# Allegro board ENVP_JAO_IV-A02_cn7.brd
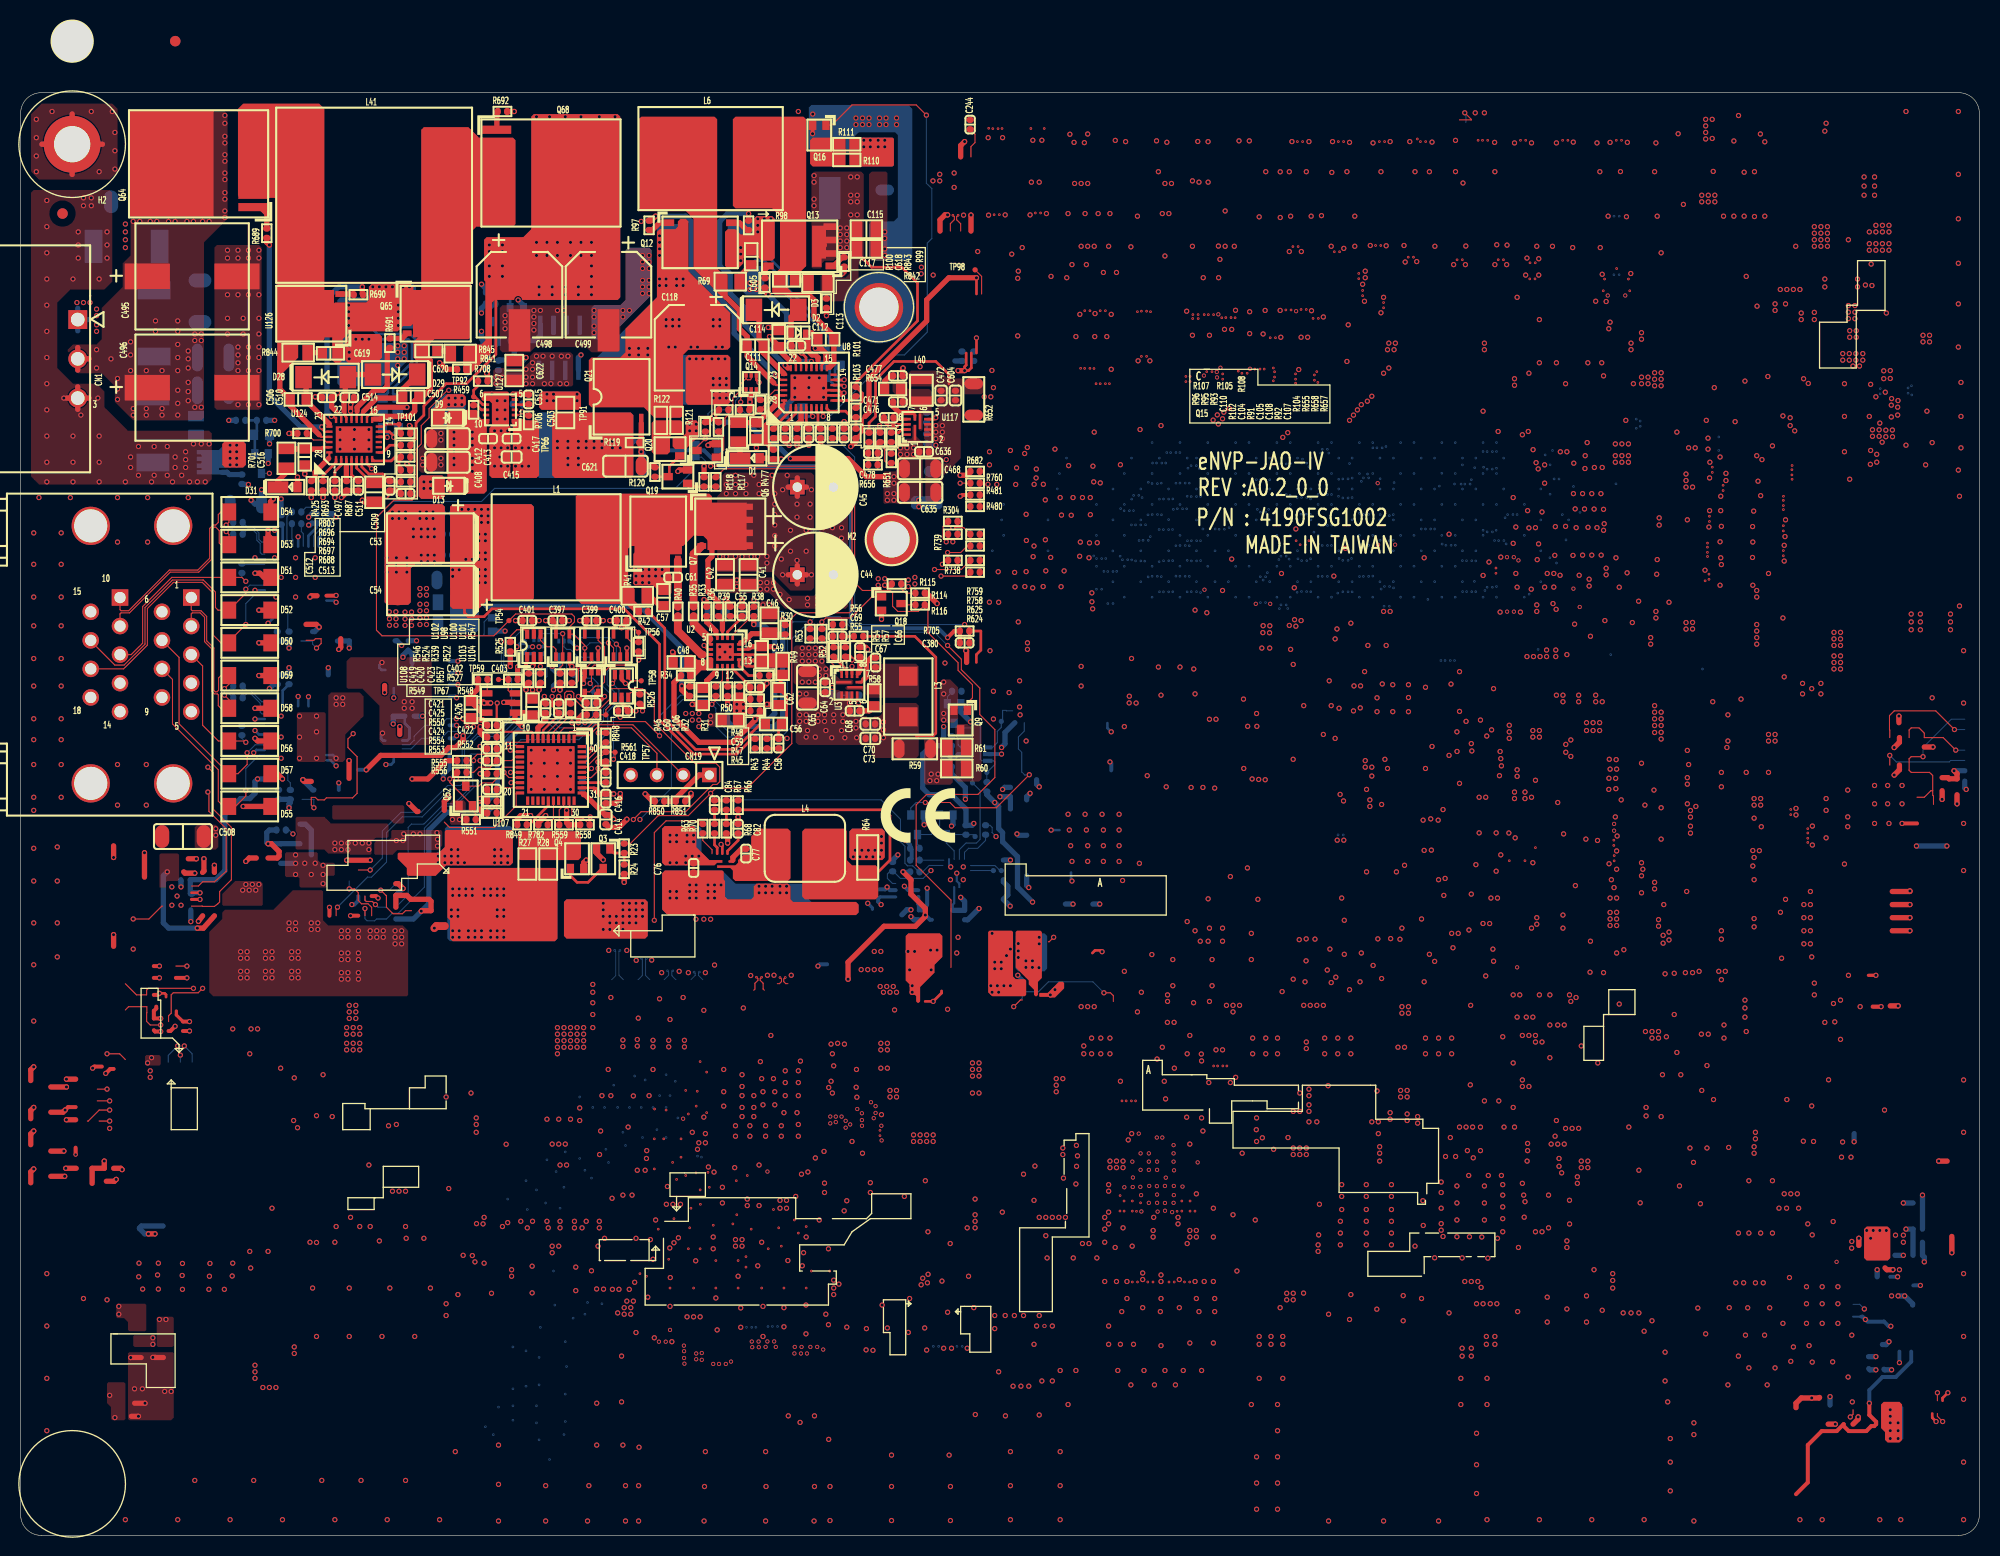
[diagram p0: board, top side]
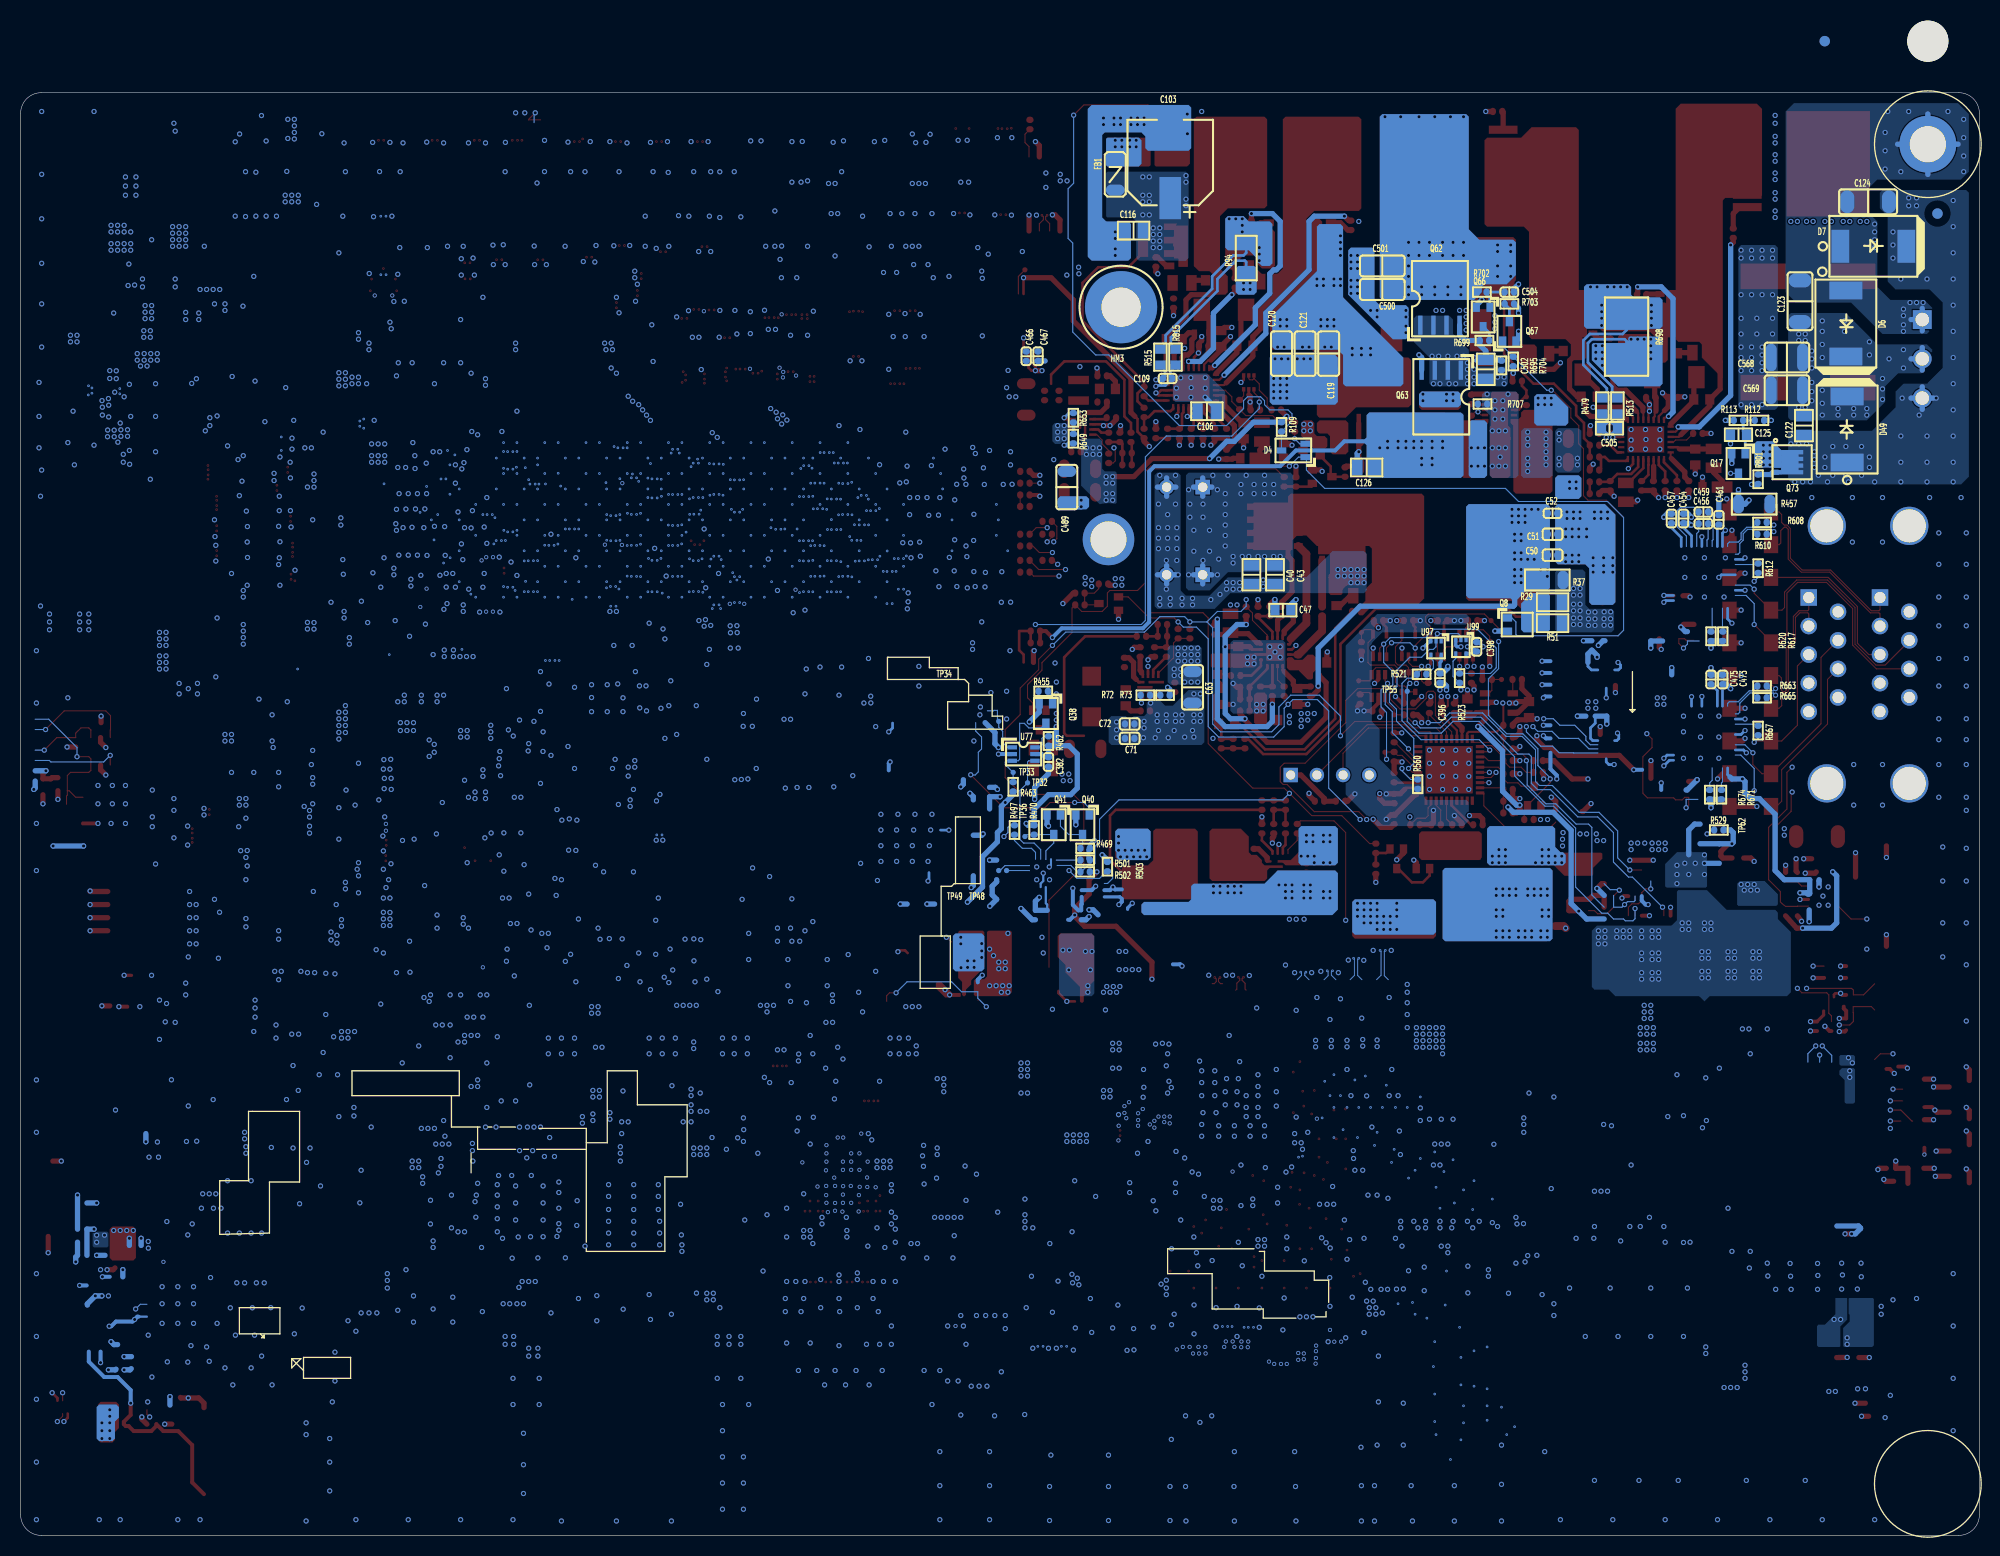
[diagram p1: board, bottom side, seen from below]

Outline 190 x 140 mm; copper layers: TOP, L2-GND1, L3-IN1, L4-VCC1, L5-VCC2, L6-IN2, L7-GND2, BOTTOM. Coordinates in mm from the lower left corner of the outline.
Outline path: 0,138 0,2 arc(0.59,0.59) 2,0 188,0 arc(189.41,0.59) 190,2 190,138 arc(189.41,139.41) 188,140 2,140 arc(0.59,139.41) 0,138

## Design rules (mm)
constraint set DEFAULT: min track width 0.102, pair gap 0.102
net group 5-6.5;3.5-3.5_DP_10.8-9: nets USB2_0_N_CON USB2_0_P_CON
net group 50OHM_RS485_D1_DP_8;8-8;8: nets D1- RX1/D1+
net group 50OHM_RS485_D2_DP_8;8-8;8: nets D2- RX2/D2+
net group 50OHM_RS485_RD1_DP_8;8-8;8: nets RS232_RD1 RS485_D1-
net group 50OHM_RS485_RD2_DP_8;8-8;8: nets RS232_RD2 RS485_D2-
net group 85OHM_M2B_USB3_RX_DP_13.1;10.A: nets M2B_USB3_RX_N M2B_USB3_RX_P
net group 85OHM_M2B_USB3_TX_DP_13.1;10.A: nets M2B_USB3_TX_N M2B_USB3_TX_P
net group 85OHM_M2E_PCIE_UPHY0_RX3_DP_1A: nets UPHY0_RX3_N UPHY0_RX3_P
net group 85OHM_M2E_PCIE_UPHY0_TX3_DP_1A: nets UPHY0_TX3_N UPHY0_TX3_P
net group 85OHM_M2E_PCIE_UPHY0_TX3_M2E_A: nets UPHY0_TX3_N_M2E UPHY0_TX3_P_M2E
net group 85OHM_M2E_UPHY0_SF_PCIE1_CLK_A: nets UPHY0_SF_PCIE1_CLK_N UPHY0_SF_PCIE1_CLK_P
net group 85OHM_MBGE_OSC_156MHZ_DP_32.4A: nets OSC_156MHZ_N OSC_156MHZ_P
net group 85OHM_MGBE_UPHY2_REFCLK2_DP_3A: nets UPHY2_REFCLK2_N UPHY2_REFCLK2_P
net group 85OHM_PCIE16_PCIE4_CLK_DP_10.A: nets PCIE4_CLK_N PCIE4_CLK_P
net group 85OHM_PCIE16_PCIE5_CLK_DP_10.A: nets PCIE5_CLK_N PCIE5_CLK_P
net group 85OHM_PCIE16_PEX_REFCLK_DP_10A: nets PEX_REFCLK_N PEX_REFCLK_P
net group 85OHM_PCIE16_PEX_TX10_DP_10.8A: nets PEX_TX10_N PEX_TX10_P
net group 85OHM_PCIE16_PEX_TX12_DP_10.8A: nets PEX_TX12_N PEX_TX12_P
net group 85OHM_PCIE16_PEX_TX14_DP_10.8A: nets PEX_TX14_N PEX_TX14_P
net group 85OHM_PCIE16_UPHY0_RX4_DP_10.A: nets UPHY0_RX4_N UPHY0_RX4_P
net group 85OHM_PCIE16_UPHY0_RX5_DP_10.A: nets UPHY0_RX5_N UPHY0_RX5_P
net group 85OHM_PCIE16_UPHY0_TX4_DP_10.A: nets UPHY0_TX4_N UPHY0_TX4_P
net group 85OHM_PCIE16_UPHY0_TX4_M2M_DPA: nets UPHY0_TX4_N_M2M UPHY0_TX4_P_M2M
net group 85OHM_PCIE16_UPHY0_TX5_DP_10.A: nets UPHY0_TX5_N UPHY0_TX5_P
net group 85OHM_PCIE16_UPHY0_TX5_M2M_DPA: nets UPHY0_TX5_N_M2M UPHY0_TX5_P_M2M
net group 85OHM_PCIE16_UPHY0_TX6_M2M_DPA: nets UPHY0_TX6_N_M2M UPHY0_TX6_P_M2M
net group 85OHM_PCIE16_UPHY0_TX7_M2M_DPA: nets UPHY0_TX7_N_M2M UPHY0_TX7_P_M2M
net group 85OHM_PCIE16_UPHY1_EP_REFCLK0A: nets UPHY1_EP_REFCLK0_N UPHY1_EP_REFCLK0_P
net group 85OHM_PCIE16_UPHY1_PEX_TX0_DPA: nets UPHY1_PEX_TX0_N UPHY1_PEX_TX0_P
net group 85OHM_PCIE16_UPHY1_PEX_TX1_DPA: nets UPHY1_PEX_TX1_N UPHY1_PEX_TX1_P
net group 85OHM_PCIE16_UPHY1_PEX_TX2_DPA: nets UPHY1_PEX_TX2_N UPHY1_PEX_TX2_P
net group 85OHM_PCIE16_UPHY1_PEX_TX3_DPA: nets UPHY1_PEX_TX3_N UPHY1_PEX_TX3_P
net group 85OHM_PCIE16_UPHY1_PEX_TX4_DPA: nets UPHY1_PEX_TX4_N UPHY1_PEX_TX4_P
net group 85OHM_PCIE16_UPHY1_PEX_TX5_DPA: nets UPHY1_PEX_TX5_N UPHY1_PEX_TX5_P
net group 85OHM_PCIE16_UPHY1_PEX_TX6_DPA: nets UPHY1_PEX_TX6_N UPHY1_PEX_TX6_P
net group 85OHM_PCIE16_UPHY1_PEX_TX7_DPA: nets UPHY1_PEX_TX7_N UPHY1_PEX_TX7_P
net group 85OHM_PCIE16_UPHY1_REFCLK0_DPA: nets UPHY1_REFCLK0_N UPHY1_REFCLK0_P
net group 85OHM_PCIE16_UPHY1_RX0_DP_10.A: nets UPHY1_RX0_N UPHY1_RX0_P
net group 85OHM_PCIE16_UPHY1_RX2_DP_10.A: nets UPHY1_RX2_N UPHY1_RX2_P
net group 85OHM_PCIE16_UPHY1_RX3_DP_10.A: nets UPHY1_RX3_N UPHY1_RX3_P
net group 85OHM_PCIE16_UPHY1_RX4_DP_10.A: nets UPHY1_RX4_N UPHY1_RX4_P
net group 85OHM_PCIE16_UPHY1_RX5_DP_10.A: nets UPHY1_RX5_N UPHY1_RX5_P
net group 85OHM_PCIE16_UPHY1_RX6_DP_10.A: nets UPHY1_RX6_N UPHY1_RX6_P
net group 85OHM_PCIE16_UPHY1_RX7_DP_10.A: nets UPHY1_RX7_N UPHY1_RX7_P
net group 85OHM_PCIE16_UPHY1_TX0_DP_10.A: nets UPHY1_TX0_N UPHY1_TX0_P
net group 85OHM_PCIE16_UPHY1_TX1_DP_10.A: nets UPHY1_TX1_N UPHY1_TX1_P
net group 85OHM_PCIE16_UPHY1_TX2_DP_10.A: nets UPHY1_TX2_N UPHY1_TX2_P
net group 85OHM_PCIE16_UPHY1_TX3_DP_10.A: nets UPHY1_TX3_N UPHY1_TX3_P
net group 85OHM_PCIE16_UPHY1_TX4_DP_10.A: nets UPHY1_TX4_N UPHY1_TX4_P
net group 85OHM_PCIE16_UPHY1_TX5_DP_10.A: nets UPHY1_TX5_N UPHY1_TX5_P
net group 85OHM_PCIE16_UPHY1_TX6_DP_10.A: nets UPHY1_TX6_N UPHY1_TX6_P
net group 85OHM_PCIE16_UPHY1_TX7_DP_10.A: nets UPHY1_TX7_N UPHY1_TX7_P
net group 85OHM_PCIE16_UPHY_RX7_DP_10.8A: nets UPHY_RX7_N UPHY_RX7_P
net group 85OHM_PCIE16_UPHY_RX8_DP_10.8A: nets UPHY_RX8_N UPHY_RX8_P
net group 85OHM_PCIE16_UPHY_RX9_DP_10.8A: nets UPHY_RX9_N UPHY_RX9_P
net group 85OHM_PCIE16_UPHY_RX10_DP_10.A: nets UPHY_RX10_N UPHY_RX10_P
net group 85OHM_PCIE16_UPHY_RX11_DP_10.A: nets UPHY_RX11_N UPHY_RX11_P
net group 85OHM_PCIE16_UPHY_TX8_DP_10.8A: nets UPHY_TX8_N UPHY_TX8_P
net group 85OHM_PCIE16_UPHY_TX9_DP_10.8A: nets UPHY_TX9_N UPHY_TX9_P
net group 85OHM_PCIE16_UPHY_TX10_DP_10.A: nets UPHY_TX10_N UPHY_TX10_P
net group 85OHM_PCIE16_UPHY_TX11_DP_10.A: nets UPHY_TX11_N UPHY_TX11_P
net group 85OHM_PCIE_16UPHY_TX7_DP_10.8A: nets UPHY_TX7_N UPHY_TX7_P
net group 85OHM_PCUE16_UPHY1_RX1_DP_10.A: nets UPHY1_RX1_N UPHY1_RX1_P
net group 85OHM_TYPEC_UPHY_TX0_DP_13.1;A: nets UPHY_TX0_N UPHY_TX0_P
net group 85OHM_TYPEC_USB_UPHY_RX0_DP_1A: nets UPHY_RX0_N UPHY_RX0_P
net group 85OHM_TYPEC_USBC1_RX1_DUT_CONA: nets USBC1_RX1_DUT_N_CON USBC1_RX1_DUT_P_CON
net group 85OHM_TYPEC_USBC1_RX1_DUT_DP_A: nets USBC1_RX1_DUT_N USBC1_RX1_DUT_P
net group 85OHM_TYPEC_USBC1_RX2_DUT_CONA: nets USBC1_RX2_DUT_N_CON USBC1_RX2_DUT_P_CON
net group 85OHM_TYPEC_USBC1_RX2_DUT_DP_A: nets USBC1_RX2_DUT_N USBC1_RX2_DUT_P
net group 85OHM_TYPEC_USBC1_TX1_DU2_CONA: nets USBC1_TX1_DU2_N_CON USBC1_TX1_DU2_P_CON
net group 85OHM_TYPEC_USBC1_TX1_DUT_AC_A: nets USBC1_TX1_DUTN USBC1_TX1_DUTP
net group 85OHM_TYPEC_USBC1_TX1_DUT_CONA: nets USBC1_TX1_DUT_N_CON USBC1_TX1_DUT_P_CON
net group 85OHM_TYPEC_USBC1_TX1_DUT_DP_A: nets USBC1_TX1_DUT_N USBC1_TX1_DUT_P
net group 85OHM_TYPEC_USBC1_TX2_DUT_AC_A: nets USBC1_TX2_DUT_N USBC1_TX2_DUT_P
net group 85OHM_TYPEC_USBC1_TX2_DUT_DP_A: nets USBC1_TX2_DUTN USBC1_TX2_DUTP
net group 85OHM_UPHY_RX_1_DP_13.1;10.8-A: nets UPHY_RX1_N UPHY_RX1_P
net group 85OHM_UPHY_TX1_DP_13.1;10.8-1A: nets UPHY_TX1N UPHY_TX1P
net group 85OHM_UPHY_TX_1_DP_13.1;10.8-A: nets UPHY_TX1_N UPHY_TX1_P
net group 85OHM_USBHIB_US_USBSS_TX_HUB_A: nets USBSS_TX_HUB_N USBSS_TX_HUB_P
net group 85OHM_USBHUB_DSP1_SSRX_DP_13.A: nets DSP1_SSRX_N DSP1_SSRX_P
net group 85OHM_USBHUB_DSP1_SSTX_DP_13.A: nets DSP1_SSTX_N DSP1_SSTX_P
net group 85OHM_USBHUB_DSP2_SSRX_DP_13.A: nets DSP2_SSRX_N DSP2_SSRX_P
net group 85OHM_USBHUB_DSP2_SSTX_DP_13.A: nets DSP2_SSTX_N DSP2_SSTX_P
net group 85OHM_USBHUB_DSP3_SSRX_DP_13.A: nets DSP3_SSRX_N DSP3_SSRX_P
net group 85OHM_USBHUB_DSP3_SSTX_DP_13.A: nets DSP3_SSTX_N DSP3_SSTX_P
net group 85OHM_USBHUB_DSP4_SSRX_DP_13.A: nets DSP4_SSRX_N DSP4_SSRX_P
net group 85OHM_USBHUB_DSP4_SSTX_DP_13.A: nets DSP4_SSTX_N DSP4_SSTX_P
net group 85OHM_USBHUB_US_UPHY0_RX2_DP_A: nets UPHY0_RX2_N UPHY0_RX2_P
net group 85OHM_USBHUB_US_UPHY0_TX2_DP_A: nets UPHY0_TX2_N UPHY0_TX2_P
net group 85OHM_USBHUB_US_UPHY_0_TX2_DPA: nets UPHY_0_TX2_N UPHY_0_TX2_P
net group 85OHM_USBHUB_US_USBSS0_TX_HUBA: nets USBSS0_TX_HUB_N USBSS0_TX_HUB_P
net group 85OHM_USBHUB_US_USBSS_RX_HUB_A: nets USBSS_RX_HUB_N USBSS_RX_HUB_P
net group 85OHM_USBHUB_USBSS_RX_A_CON1_A: nets USBSS_RX_A_CON1_N USBSS_RX_A_CON1_P
net group 85OHM_USBHUB_USBSS_RX_A_CON2_A: nets USBSS_RX_A_CON2_N USBSS_RX_A_CON2_P
net group 85OHM_USBHUB_USBSS_RX_B_CON3_A: nets USBSS_RX_B_CON3_N USBSS_RX_B_CON3_P
net group 85OHM_USBHUB_USBSS_RX_B_CON4_A: nets USBSS_RX_B_CON4_N USBSS_RX_B_CON4_P
net group 85OHM_USBHUB_USBSS_TX_A_1_DP_A: nets USBSS_TX_A_1_N USBSS_TX_A_1_P
net group 85OHM_USBHUB_USBSS_TX_A_2_DP_A: nets USBSS_TX_A_2_N USBSS_TX_A_2_P
net group 85OHM_USBHUB_USBSS_TX_A_CON1_A: nets USBSS_TX_A_CON1_N USBSS_TX_A_CON1_P
net group 85OHM_USBHUB_USBSS_TX_A_CON2_A: nets USBSS_TX_A_CON2_N USBSS_TX_A_CON2_P
net group 85OHM_USBHUB_USBSS_TX_B_3_DP_A: nets USBSS_TX_B_3_N USBSS_TX_B_3_P
net group 85OHM_USBHUB_USBSS_TX_B_4_DP_A: nets USBSS_TX_B_4_N USBSS_TX_B_4_P
net group 85OHM_USBHUB_USBSS_TX_B_CON3_A: nets USBSS_TX_B_CON3_N USBSS_TX_B_CON3_P
net group 85OHM_USBHUB_USBSS_TX_B_CON4_A: nets USBSS_TX_B_CON4_N USBSS_TX_B_CON4_P
net group 90OHM_FORCE_USB2_0_DP_10.8;10A: nets USB2_0_N USB2_0_P
net group 90OHM_M2B_USB2_0_D_DP_10.8;10A: nets USB2_1_DN USB2_1_DP
net group 90OHM_M2B_USB_D_DP_10.8;10.8-A: nets M2B_USB_DN M2B_USB_DP
net group 90OHM_M2E_USB2_2_DP_10.8;10.8A: nets USB2_2_N USB2_2_P
net group 90OHM_USBHUB_DSP1_D_DP_10.8;1A: nets DSP1_DN DSP1_DP
net group 90OHM_USBHUB_DSP2_D_DP_10.8;1A: nets DSP2_DN DSP2_DP
net group 90OHM_USBHUB_DSP3_D_DP_10.8;1A: nets DSP3_DN DSP3_DP
net group 90OHM_USBHUB_DSP4_D_DP_10.8;1A: nets DSP4_DN DSP4_DP
net group 90OHM_USBHUB_USB1_A_DP_10.8;1A: nets USB1_A_N USB1_A_P
net group 90OHM_USBHUB_USB2_3_DP_10.8;1A: nets USB2_3_N USB2_3_P
net group 90OHM_USBHUB_USB2_3_HUB_DP_10A: nets USB2_3_HUB_N USB2_3_HUB_P
net group 90OHM_USBHUB_USB2_A_DP_10.8;1A: nets USB2_A_N USB2_A_P
net group 90OHM_USBHUB_USB3_B_DP_10.8;1A: nets USB3_B_N USB3_B_P
net group 90OHM_USBHUB_USB4_B_DP_10.8;1A: nets USB4_B_N USB4_B_P
net group 100OHM_CSI_0_CLK_DP_8.1;8.1-9;9: nets CSI_0_CLK_N CSI_0_CLK_P
net group 100OHM_CSI_0_D0_DP_8.1;8.1-9;9: nets CSI_0_D0_N CSI_0_D0_P
net group 100OHM_CSI_0_D1_DP_8.1;8.1-9;9: nets CSI_0_D1_N CSI_0_D1_P
net group 100OHM_CSI_1_CLK_DP_8.1;8.1-9;9: nets CSI_1_CLK_N CSI_1_CLK_P
net group 100OHM_CSI_1_D0_DP_8.1;8.1-9;9: nets CSI_1_D0_N CSI_1_D0_P
net group 100OHM_CSI_1_D1_DP_8.1;8.1-9;9: nets CSI_1_D1_N CSI_1_D1_P
net group 100OHM_CSI_2_CLK_DP_8.1;8.1-9;9: nets CSI_2_CLK_N CSI_2_CLK_P
net group 100OHM_CSI_2_D0_DP_8.1;8.1-9;9: nets CSI_2_D0_N CSI_2_D0_P
net group 100OHM_CSI_2_D1_DP_8.1;8.1-9;9: nets CSI_2_D1_N CSI_2_D1_P
net group 100OHM_CSI_3_CLK_DP_8.1;8.1-9;9: nets CSI_3_CLK_N CSI_3_CLK_P
net group 100OHM_CSI_3_D0_DP_8.1;8.1-9;9: nets CSI_3_D0_N CSI_3_D0_P
net group 100OHM_CSI_3_D1_DP_8.1;8.1-9;9: nets CSI_3_D1_N CSI_3_D1_P
net group 100OHM_CSI_4_CLK_DP_8.1;8.1-9;9: nets CSI_4_CLK_N CSI_4_CLK_P
net group 100OHM_CSI_4_D0_DP_8.1;8.1-9;9: nets CSI_4_D0_N CSI_4_D0_P
net group 100OHM_CSI_4_D1_DP_8.1;8.1-9;9: nets CSI_4_D1_N CSI_4_D1_P
net group 100OHM_CSI_5_CLK_DP_8.1;8.1-9;9: nets CSI_5_CLK_N CSI_5_CLK_P
net group 100OHM_CSI_5_D0_DP_8.1;8.1-9;9: nets CSI_5_D0_N CSI_5_D0_P
net group 100OHM_CSI_5_D1_DP_8.1;8.1-9;9: nets CSI_5_D1_N CSI_5_D1_P
net group 100OHM_CSI_6_CLK_DP_8.1;8.1-9;9: nets CSI_6_CLK_N CSI_6_CLK_P
net group 100OHM_CSI_6_D0_DP_8.1;8.1-9;9: nets CSI_6_D0_N CSI_6_D0_P
net group 100OHM_CSI_6_D1_DP_8.1;8.1-9;9: nets CSI_6_D1_N CSI_6_D1_P
net group 100OHM_CSI_7_CLK_DP_8.1;8.1-9;9: nets CSI_7_CLK_N CSI_7_CLK_P
net group 100OHM_CSI_7_D0_DP_8.1;8.1-9;9: nets CSI_7_D0_N CSI_7_D0_P
net group 100OHM_CSI_7_D1_DP_8.1;8.1-9;9: nets CSI_7_D1_N CSI_7_D1_P
net group 100OHM_GBE_PHY1_A_DP_10.8;10.A: nets GBE_PHY1_A_N GBE_PHY1_A_P
net group 100OHM_GBE_PHY1_B_DP_10.8;10.A: nets GBE_PHY1_B_N GBE_PHY1_B_P
net group 100OHM_GBE_PHY1_C_DP_10.8;10.A: nets GBE_PHY1_C_N GBE_PHY1_C_P
net group 100OHM_GBE_PHY1_D_DP_10.8;10.A: nets GBE_PHY1_D_N GBE_PHY1_D_P
net group 100OHM_GBE_PHY2_A_DP_10.8;10.A: nets GBE_PHY2_A_N GBE_PHY2_A_P
net group 100OHM_GBE_PHY2_B_DP_10.8;10.A: nets GBE_PHY2_B_N GBE_PHY2_B_P
net group 100OHM_GBE_PHY2_C_DP_10.8;10.A: nets GBE_PHY2_C_N GBE_PHY2_C_P
net group 100OHM_GBE_PHY2_D_DP_10.8;10.A: nets GBE_PHY2_D_N GBE_PHY2_D_P
net group 100OHM_HDMI_DP0_CLK_DP_13.5;1A: nets HDMI_DP0_CLKN HDMI_DP0_CLKP
net group 100OHM_HDMI_DP0_TX0_DP_13.5;1A: nets HDMI_DP0_TX0N HDMI_DP0_TX0P
net group 100OHM_HDMI_DP0_TX1_DP_13.5;1A: nets HDMI_DP0_TX1N HDMI_DP0_TX1P
net group 100OHM_HDMI_DP0_TX2_DP_13.5;1A: nets HDMI_DP0_TX2N HDMI_DP0_TX2P
net group 100OHM_MGBE_PCIE_AQR113C_RX_DA: nets AQR113C_RX_N AQR113C_RX_P
net group 100OHM_MGBE_PCIE_AQR113C_TX_DA: nets AQR113C_TX_N AQR113C_TX_P
net group 100OHM_MGBE_PCIE_UPHY_RX6_DP_A: nets UPHY_RX6_N UPHY_RX6_P
net group 100OHM_RE_HDMI_CLK_DP_13.5;13A: nets RE_HDMI_DP0_CLKN RE_HDMI_DP0_CLKP
net group 100OHM_RE_HDMI_TX0_DP_13.5;13A: nets RE_HDMI_DP0_TX0N RE_HDMI_DP0_TX0P
net group 100OHM_RE_HDMI_TX1_DP_13.5;13A: nets RE_HDMI_DP0_TX1N RE_HDMI_DP0_TX1P
net group 100OHM_RE_HDMI_TX2_DP_13.5;13A: nets RE_HDMI_DP0_TX2N RE_HDMI_DP0_TX2P
net group 100OHM_RE_OUT_HDMI_DP0_CLK_DPA: nets OUT_HDMI_DP0_CLKN OUT_HDMI_DP0_CLKP
net group 100OHM_RE_OUT_HDMI_DP0_TX0_DPA: nets OUT_HDMI_DP0_TX0N OUT_HDMI_DP0_TX0P
net group 100OHM_RE_OUT_HDMI_DP0_TX1_DPA: nets OUT_HDMI_DP0_TX1N OUT_HDMI_DP0_TX1P
net group 120OHM_CAN_BUS_DB9_DP_10.5;10A: nets CANH_DB9 CANL_DB9
net group 120OHM_CAN_BUS_DP_10.5;10.5-6;6: nets CANH CANL
net group DIFF_AUD_HPO_DP_10;10-10;10: nets AUD_HPOL AUD_HPOR
net group DIFF_AUD_HPO_HDA_DP_10;10-10;10: nets AUD_HPOL_HDA AUD_HPOR_HDA
net group GPIO24_XFI2_MDIO_12;12-10.5;1A: nets GPIO24_XFI2_MDIO GPIO24_XFI2_MDIO_CVM
net group I2S1_DIN_8;8-7;7: nets I2S1_DIN I2S1_DIN_CDC
net group I2S1_DOUT_8;8-7;7: nets I2S1_DOUT I2S1_DOUT_CDC
net group I2S1_FS_8;8-7;7: nets I2S1_FS I2S1_FS_CDC
net group I2S1_SCLK_8;8-7;7: nets I2S1_SCLK I2S1_SCLK_CDC
net group MGBE-M: nets UPHY_TX6_N UPHY_TX6_P
net group RE_OUT_HDMI_DP0_TX2_DP_13.5;1A: nets OUT_HDMI_DP0_TX2N OUT_HDMI_DP0_TX2P
net group USB2: nets USB2_1_N USB2_1_P
net group 1V2_DCVDD_15;15-15;15: nets 1V2_DCVDD
net group 1V8_AVDD_15;15-15;15: nets 1V8_AVDD
net group 1V8_CPVDD_15;15-15;15: nets 1V8_CPVDD
net group 3V3_AO_BODE_12;12-10.5;10.5: nets 3V3_AO_BODE
net group 3V3_AO_FB_12;12-10.5;10.5: nets 3V3_AO_FB
net group 3V3_AO_FB_R_12;12-10.5;10.5: nets 3V3_AO_FB_R
net group 5V_SPKVDD_30;30-30;30: nets 5V_SPKVDD
net group 15-15: nets AUDIO_VREF_DAC
net group AUD_MCLK01_CDC_8;8-7;7: nets AUD_MCLK01_CDC
net group AUDIO_JD1_12;12-10.5;10.5: nets AUDIO_JD1
net group BAT_CONN_LIM_20;20-20;20: nets BAT_CONN_LIM
net group BT_DEV_WAKE_M2E_12;12-10.5;10.5: nets BT_DEV_WAKE_M2E
net group BT_RST_N_M2E_CON_12;12-10.5;1A: nets BT_RST_N_M2E_CON
net group BT_WAKE_AP_M2E_CON_12;12-10.5A: nets BT_WAKE_AP_M2E_CON
net group BUCK_1V1_BODE_12;12-10.5;10.5: nets BUCK_1V1_BODE
net group BUCK_1V1_FB_12;12-10.5;10.5: nets BUCK_1V1_FB
net group BUCK_1V1_FB_R_12;12-10.5;10.5: nets BUCK_1V1_FB_R
net group BUTTON_POWER_ON_N_12;12-10.5;A: nets BUTTON_POWER_ON_N
net group BUTTON_POWER_ON_N_CON_12;12-1A: nets BUTTON_POWER_ON_N_CON
net group BUTTON_POWER_ON_N_KEY_12;12-1A: nets BUTTON_POWER_ON_N_KEY
net group CAM0_RST_12;12-10.5;10.5: nets CAM0_RST
net group CAM1_RST_12;12-10.5;10.5: nets CAM1_RST
net group CAM_2V8_BODE_12;12-10.5;10.5: nets CAM_2V8_BODE
net group CAM_2V8_FB_12;12-10.5;10.5: nets CAM_2V8_FB
net group CAM_2V8_FB_R_12;12-10.5;10.5: nets CAM_2V8_FB_R
net group CAM_BACKLIGHT_PWM_12;12-10.5;A: nets CAM_BACKLIGHT_PWM
net group CAM_SPI_CS0_8.1;8.1-6;6: nets CAM_SPI_CS0
net group CAM_SPI_MISO_8.1;8.1-6;6: nets CAM_SPI_MISO
net group CAM_SPI_MOSI_8.1;8.1-6;6: nets CAM_SPI_MOSI
net group CAM_SPI_SCK_8.1;8.1-6;6: nets CAM_SPI_SCK
net group CAN0_DIN_12;12-10.5;10.5: nets CAN0_DIN
net group CAN0_DOUT_12;12-10.5;10.5: nets CAN0_DOUT
net group CARRIER_POWER_ON_12;12-10.5;1A: nets CARRIER_POWER_ON
net group CARRIER_SHUTDOWN_N_12;12-10.5A: nets CARRIER_SHUTDOWN_N
net group CLK_32K_OSC_M2E_12;12-10.5;10.5: nets CLK_32K_OSC_M2E
net group CLK_32K_OSC_M2M_12;12-10.5;10.5: nets CLK_32K_OSC_M2M
net group COM_20;20-20;20: nets COM
net group CVM_PRSNT_12;12-10.5;10.5: nets CVM_PRSNT
net group DC_IN_EC_N_12;12-10.5;10.5: nets DC_IN_EC_N
net group DC_IN_GATE_CCG4_12;12-10.5;10.5: nets DC_IN_GATE_CCG4 DC_IN_GATE_CCG4_CTRL DC_IN_GATE_OE
net group DC_SRC_SEL_12;12-10.5;10.5: nets DC_SRC_SEL
net group DI_1_20;20-20;20: nets DI_1
net group DI_2_20;20-20;20: nets DI_2
net group DI_3_20;20-20;20: nets DI_3
net group DI_4_20;20-20;20: nets DI_4
net group DO1_OUT_40;40-40;40: nets DO1_OUT
net group DO2_OUT_40;40-40;40: nets DO2_OUT
net group DO3_OUT_40;40-40;40: nets DO3_OUT
net group DO4_OUT_40;40-40;40: nets DO4_OUT
net group DP1_HPD_GP77_XFI3_MDIO_12;12-A: nets DP1_HPD_GP77_XFI3_MDIO
net group DP2_AUX_CH_N_I2C6_DAT_8;8-7;7: nets DP2_AUX_CH_N_I2C6_DAT
net group DP2_AUX_CH_P_I2C6_CLK_8;8-7;7: nets DP2_AUX_CH_P_I2C6_CLK
net group DP2_HPD_CH0_HPD_12;12-10.5;10.5: nets DP2_HPD_CH0_HPD
net group DP2_HPD_GP80_XFI3_MDC_12;12-1A: nets DP2_HPD_GP80_XFI3_MDC
net group ECSPI2_CS0_8.1;8.1-6;6: nets ECSPI2_SS0
net group ECSPI2_CS0_LV_8.1;8.1-6;6: nets ECSPI2_SS0_LV
net group ECSPI2_MISO_8.1;8.1-6;6: nets ECSPI2_MISO
net group ECSPI2_MISO_LV_8.1;8.1-6;6: nets ECSPI2_MISO_LV
net group ECSPI2_MOSI_8.1;8.1-6;6: nets ECSPI2_MOSI
net group ECSPI2_MOSI_LV_8.1;8.1-6;6: nets ECSPI2_MOSI_LV
net group ECSPI2_SCLK_8.1;8.1-6;6: nets ECSPI2_SCLK
net group ECSPI2_SCLK_LV_8.1;8.1-6;6: nets ECSPI2_SCLK_LV
net group EFM8_FORCE_SHUTDOWN_12;12-10.A: nets EFM8_FORCE_SHUTDOWN
net group EFM8_MODULE_POWER_ON_12;12-10A: nets EFM8_MODULE_POWER_ON
net group EFM8_PSHOLD_12;12-10.5;10.5: nets EFM8_PSHOLD
net group EFM8_RST_MON_12;12-10.5;10.5: nets EFM8_RST_MON
net group EFM8SB10_C2CK_12;12-10.5;10.5: nets EFM8SB10_C2CK
net group ETH_WOL_EN_N_12;12-10.5;10.5: nets ETH_WOL_EN_N
net group ETH_WOL_EN_STATUS_12;12-10.5;A: nets ETH_WOL_EN_STATUS
net group FAN_PWM_12;12-10.5;10.5: nets FAN_PWM
net group FORCE_RECOVERY_N_12;12-10.5;1A: nets FORCE_RECOVERY_N
net group FORCE_RECOVERY_N_CON_12;12-10A: nets FORCE_RECOVERY_N_CON
net group FORCE_RECOVERY_N_KEY_12;12-10A: nets FORCE_RECOVERY_N_KEY
net group GB_AVDDH_10;10-10;10: nets GB_AVDDH
net group GB_MDC_12;12-10.5;10.5: nets GB_MDC
net group GB_MDIO_12;12-10.5;10.5: nets GB_MDIO
net group GB_PHY_RST_N_12;12-10.5;10.5: nets GB_PHY_RST_N
net group GB_PHY_RSTN_12;12-10.5;10.5: nets GB_PHY_RSTN
net group GB_RX_CTL_12;12-10.5;10.5: nets GB_RX_CTL
net group GB_RXC_12;12-10.5;10.5: nets GB_RXC
net group GB_RXD0_12;12-10.5;10.5: nets GB_RXD0
net group GB_RXD1_12;12-10.5;10.5: nets GB_RXD1
net group GB_RXD2_12;12-10.5;10.5: nets GB_RXD2
net group GB_RXD3_12;12-10.5;10.5: nets GB_RXD3
net group GB_TX_CTL_12;12-10.5;10.5: nets GB_TX_CTL
net group GB_TXC_12;12-10.5;10.5: nets GB_TXC
net group GB_TXD0_12;12-10.5;10.5: nets GB_TXD0
net group GB_TXD1_12;12-10.5;10.5: nets GB_TXD1
net group GB_TXD2_12;12-10.5;10.5: nets GB_TXD2
net group GB_TXD3_12;12-10.5;10.5: nets GB_TXD3
net group GP_PWM4*_12;12-10.5;10.5: nets GP_PWM4*
net group GP_PWM4_12;12-10.5;10.5: nets GP_PWM4
net group GPIO03_XFI2_MDC_12;12-10.5;10.5: nets GPIO03_XFI2_MDC
net group GPIO19_XFI1_MDC_12;12-10.5;10.5: nets GPIO19_XFI1_MDC
net group GPIO25_XFI0_MDIO_12;12-10.5;1A: nets GPIO25_XFI0_MDIO
net group GPIO26_XFI0_MDC_12;12-10.5;10.5: nets GPIO26_XFI0_MDC
net group GPIO33_XFI1_MDIO_12;12-10.5;1A: nets GPIO33_XFI1_MDIO
net group GPIO_PMOS_ON_12;12-10.5;10.5: nets GPIO_PMOS_ON
net group GPIO_PMOS_ON_CTRL_12;12-10.5;A: nets GPIO_PMOS_ON_CTRL
net group HDMI: nets HDMI_CLKN_CN HDMI_CLKP_CN HDMI_DP0_CLK_N HDMI_DP0_CLK_P HDMI_DP0_TX0_N HDMI_DP0_TX0_P HDMI_DP0_TX1_N HDMI_DP0_TX1_P HDMI_DP0_TX2_N HDMI_DP0_TX2_P HDMI_TX0_N HDMI_TX0_P HDMI_TX1_N HDMI_TX1_P HDMI_TX2_N HDMI_TX2_P
net group HDMI_DDC_SCL_CN_8;8-7;7: nets HDMI_DDC_SCL_CN
net group HDMI_DDC_SDA_CN_8;8-7;7: nets HDMI_DDC_SDA_CN
net group HUB_I2C_CLK_8;8-7;7: nets HUB_I2C_CLK
net group HUB_I2C_DAT_8;8-7;7: nets HUB_I2C_DAT
net group I2C_CLK_M2E_8;8-7;7: nets I2C_CLK_M2E
net group I2C_GP1_CLK_8;8-7;7: nets I2C_GP1_CLK
net group I2C_GP1_DAT_8;8-7;7: nets I2C_GP1_DAT
net group I2C_GP2_CLK_3V3_8;8-7;7: nets I2C_GP2_CLK_3V3
net group I2C_GP2_CLK_8;8-7;7: nets I2C_GP2_CLK
net group I2C_GP2_CLK_IO_8;8-7;7: nets I2C_GP2_CLK_IO
net group I2C_GP2_CLK_M2M_8;8-7;7: nets I2C_GP2_CLK_M2M
net group I2C_GP2_DAT_3V3_8;8-7;7: nets I2C_GP2_DAT_3V3
net group I2C_GP2_DAT_8;8-7;7: nets I2C_GP2_DAT
net group I2C_GP2_DAT_IO_8;8-7;7: nets I2C_GP2_DAT_IO
net group I2C_GP2_DAT_M2M_8;8-7;7: nets I2C_GP2_DAT_M2M
net group I2C_GP3_CLK_8;8-7;7: nets I2C_GP3_CLK
net group I2C_GP3_CLK_PEX_3V3_8;8-7;7: nets I2C_GP3_CLK_PEX_3V3
net group I2C_GP3_DAT_8;8-7;7: nets I2C_GP3_DAT
net group I2C_GP3_DAT_PEX_3V3_8;8-7;7: nets I2C_GP3_DAT_PEX_3V3
net group I2C_GP8_CLK_8;8-7;7: nets I2C_GP8_CLK
net group I2C_GP8_DAT_8;8-7;7: nets I2C_GP8_DAT
net group I2C_GP9_CLK_8;8-7;7: nets I2C_GP9_CLK
net group I2C_GP9_DAT_8;8-7;7: nets I2C_GP9_DAT
net group I2C_SCL_CDC_8;8-7;7: nets I2C_SCL_CDC
net group I2C_SDA_CDC_8;8-7;7: nets I2C_SDA_CDC
net group I2C_SDA_M2E_8;8-7;7: nets I2C_SDA_M2E
net group I2S4_DIN_8;8-7;7: nets I2S4_DIN
net group I2S4_DOUT_8;8-7;7: nets I2S4_DOUT
net group I2S4_FS_8;8-7;7: nets I2S4_FS
net group I2S4_SCLK_8;8-7;7: nets I2S4_SCLK
net group IO_EXPAN_P3_8;8-7;7: nets IO_EXPAN_P3
net group IO_EXPAN_P5_12;12-10.5;10.5: nets IO_EXPAN_P5
net group IO_EXPAN_RSTN_12;12-10.5;10.5: nets IO_EXPAN_RSTN
net group JTAG_TCK_12;12-10.5;10.5: nets JTAG_TCK
net group JTAG_TDI_4;12-3.5;10.5: nets JTAG_TDI
net group JTAG_TDO_4;12-3.5;10.5: nets JTAG_TDO
net group JTAG_TMS_4;12-3.5;10.5: nets JTAG_TMS
net group JTAG_TRST_N_12;12-10.5;10.5: nets JTAG_TRST_N
net group M2_B_RST#_8;8-7;7: nets M2_B_RST#
net group M2B_RST#_12;12-10.5;10.5: nets M2B_RST#
net group M2B_RST_#_12;12-10.5;10.5: nets M2B_RST_#
net group M2B_USIM_CLK_12;12-10.5;10.5: nets M2B_USIM_CLK
net group M2E_SDIO_CLK_12;12-10.5;10.5: nets M2E_SDIO_CLK
net group M2E_SDIO_CMD_4;12-3.5;10.5: nets M2E_SDIO_CMD
net group M2E_SDIO_D0_4;12-3.5;10.5: nets M2E_SDIO_D0
net group M2E_SDIO_D1_4;12-3.5;10.5: nets M2E_SDIO_D1
net group M2E_SDIO_D2_4;12-3.5;10.5: nets M2E_SDIO_D2
net group M2E_SDIO_D3_4;12-3.5;10.5: nets M2E_SDIO_D3
net group MCLK01_AUDIO_MCLK_8;8-7;7: nets MCLK01_AUDIO_MCLK
net group MCLK02_CAM0_MCLK_12;12-10.5;1A: nets MCLK02_CAM0_MCLK
net group MCLK02_MCLK_12;12-10.5;10.5: nets MCLK02_MCLK
net group MCLK03_CAM1_MCLK_12;12-10.5;1A: nets MCLK03_CAM1_MCLK
net group MCLK03_MCLK_12;12-10.5;10.5: nets MCLK03_MCLK
net group MCLK04_CAM2_MCLK_12;12-10.5;1A: nets MCLK04_CAM2_MCLK
net group MCLK04_MCLK_12;12-10.5;10.5: nets MCLK04_MCLK
net group MCU_BOOT0_8;8-7;7: nets MCU_BOOT0
net group MCU_I2C_CLK_8;8-7;7: nets MCU_I2C_CLK
net group MCU_I2C_DAT_8;8-7;7: nets MCU_I2C_DAT
net group MCU_RST_12;12-10.5;10.5: nets MCU_RST
net group MCU_RST_IN_12;12-10.5;10.5: nets MCU_RST_IN
net group MCU_SWCLK_12;12-10.5;10.5: nets MCU_SWCLK
net group MCU_SWDIO_12;12-10.5;10.5: nets MCU_SWDIO
net group MGBE-CONN: nets MGBE_PHY_A_N MGBE_PHY_A_P MGBE_PHY_B_N MGBE_PHY_B_P MGBE_PHY_C_N MGBE_PHY_C_P MGBE_PHY_D_N MGBE_PHY_D_P
net group MGBE_A_I2C_DAT_8;8-7;7: nets MGBE_A_I2C_DAT
net group MGBE_A_I2C_SCL_8;8-7;7: nets MGBE_A_I2C_SCL
net group MGBE_A_JTAG_TCK_12;12-10.5;10.5: nets MGBE_A_JTAG_TCK
net group MGBE_A_JTAG_TDI_4;12-3.5;10.5: nets MGBE_A_JTAG_TDI
net group MGBE_A_JTAG_TDO_4;12-3.5;10.5: nets MGBE_A_JTAG_TDO
net group MGBE_A_JTAG_TMS_4;12-3.5;10.5: nets MGBE_A_JTAG_TMS
net group MGBE_A_JTAG_TRST_12;12-10.5;1A: nets MGBE_A_JTAG_TRST
net group MGBE_A_PHY_MDC_12;12-10.5;10.5: nets MGBE_A_PHY_MDC
net group MGBE_A_PHY_MDIO_12;12-10.5;10.5: nets MGBE_A_PHY_MDIO
net group MGBE_A_RST_N_12;12-10.5;10.5: nets MGBE_A_RST_N
net group MGBE_A_SPI_CE*_8.1;8.1-6;6: nets MGBE_A_SPI_CE*
net group MGBE_A_SPI_SCLK_8.1;8.1-6;6: nets MGBE_A_SPI_SCLK
net group MGBE_A_SPI_SIN_8.1;8.1-6;6: nets MGBE_A_SPI_SIN
net group MGBE_A_SPI_SOUT_8.1;8.1-6;6: nets MGBE_A_SPI_SOUT
net group MICVDD_15;15-15;15: nets MICVDD
net group MOD_SHUTDOWN_N_3V3_12;12-10.5A: nets MOD_SHUTDOWN_N_3V3
net group MOD_SHUTDOWN_N_12;12-10.5;10.5: nets MOD_SHUTDOWN_N
net group MODULE_POWER_ON_12;12-10.5;10.5: nets MODULE_POWER_ON
net group N7262523_12;12-10.5;10.5: nets N7262523
net group N7262571_12;12-10.5;10.5: nets N7262571
net group N7262737_12;12-10.5;10.5: nets N7262737
net group N7262987_12;12-10.5;10.5: nets N7262987
net group N7364639_12;12-10.5;10.5: nets N7364639
net group N7364675_12;12-10.5;10.5: nets N7364675
net group N7364853_12;12-10.5;10.5: nets N7364853
net group N7461291_12;12-10.5;10.5: nets N7461291
net group N7488017_12;12-10.5;10.5: nets N7488017
net group N7514993_8;8-7;7: nets N7514993
net group N7514997_8;8-7;7: nets N7514997
net group N7772552_20;20-20;20: nets N7772552
net group N7774424_20;20-20;20: nets N7774424
net group N7777074_20;20-20;20: nets N7777074
net group N7777496_20;20-20;20: nets N7777496
net group N7854424_8;8-7;7: nets N7854424
net group N7855347_8;8-7;7: nets N7855347
net group N8449696_20;20-20;20: nets N8449696
net group N8449700_20;20-20;20: nets N8449700
net group N8450796_20;20-20;20: nets N8450796
net group N8450804_20;20-20;20: nets N8450804
net group PCIE1_RST_N_12;12-10.5;10.5: nets PCIE1_RST_N
net group PCIE4_RST_N_12;12-10.5;10.5: nets PCIE4_RST_N
net group PCIE5_RST_N_12;12-10.5;10.5: nets PCIE5_RST_N
net group PCIE5_RST_N_CON_12;12-10.5;10.5: nets PCIE5_RST_N_CON
net group PCIE_PRSNT_12;12-10.5;10.5: nets PCIE_PRSNT
net group PCIE_PRSNT_CON_L_12;12-10.5;1A: nets PCIE_PRSNT_CON_L
net group PCIE_PRSNT_INV_12;12-10.5;10.5: nets PCIE_PRSNT_INV
net group PCIE_PRSNT_L_12;12-10.5;10.5: nets PCIE_PRSNT_L
net group PCIE_TCK_12;12-10.5;10.5: nets PCIE_TCK
net group PCIE_TDI_4;12-3.5;10.5: nets PCIE_TDI
net group PCIE_TDO_4;12-3.5;10.5: nets PCIE_TDO
net group PCIE_TMS_4;12-3.5;10.5: nets PCIE_TMS
net group PCIE_TRST#_12;12-10.5;10.5: nets PCIE_TRST#
net group PD_SWD_CLK_8;8-7;7: nets PD_SWD_CLK
net group PD_SWD_IO_8;8-7;7: nets PD_SWD_IO
net group PS_0V7_BODE_12;12-10.5;10.5: nets PS_0V7_BODE
net group PS_0V7_FB_12;12-10.5;10.5: nets PS_0V7_FB
net group PS_0V7_FB_R_12;12-10.5;10.5: nets PS_0V7_FB_R
net group PS_1V8_BODE_12;12-10.5;10.5: nets PS_1V8_BODE
net group PS_1V8_FB_12;12-10.5;10.5: nets PS_1V8_FB
net group PS_1V8_FB_R_12;12-10.5;10.5: nets PS_1V8_FB_R
net group PS_2V5_BODE_12;12-10.5;10.5: nets PS_2V5_BODE
net group PS_2V5_FB_12;12-10.5;10.5: nets PS_2V5_FB
net group PS_2V5_FB_R_12;12-10.5;10.5: nets PS_2V5_FB_R
net group PS_12V_FB_12;12-10.5;10.5: nets PS_12V_FB
net group PS_20V_FB_12;12-10.5;10.5: nets PS_20V_FB
net group PWM_FAN_INV_D_12;12-10.5;10.5: nets PWM_FAN_INV_D
net group RGMII-TD: nets RGMII_TD0 RGMII_TD1 RGMII_TD2 RGMII_TD3 RGMII_TX_CTL RGMII_TXC
net group RGMII_RD0_13.5;13.5-15;15: nets RGMII_RD0
net group RGMII_RD1_13.5;13.5-15;15: nets RGMII_RD1
net group RGMII_RD2_13.5;13.5-15;15: nets RGMII_RD2
net group RGMII_RD3_13.5;13.5-15;15: nets RGMII_RD3
net group RGMII_RX_CTL_13.5;13.5-15;15: nets RGMII_RX_CTL
net group RGMII_RXC_13.5;13.5-15;15: nets RGMII_RXC
net group RGMII_SMA_MDC_12;12-10.5;10.5: nets RGMII_SMA_MDC
net group RGMII_SMA_MDIO_12;12-10.5;10.5: nets RGMII_SMA_MDIO
net group SD: nets SDMMC1_CLK SDMMC1_CMD SDMMC1_D0 SDMMC1_D1 SDMMC1_D2 SDMMC1_D3
net group SD_DET_N_10.8;10.8-9;9: nets SD_DET_N
net group SDCARD_CLK_10.8;10.8-9;9: nets SDCARD_CLK
net group SDCARD_CMD_10.8;10.8-9;9: nets SDCARD_CMD
net group SDCARD_D0_10.8;10.8-9;9: nets SDCARD_D0
net group SDCARD_D1_10.8;10.8-9;9: nets SDCARD_D1
net group SDCARD_D2_10.8;10.8-9;9: nets SDCARD_D2
net group SDCARD_D3_10.8;10.8-9;9: nets SDCARD_D3
net group SDCARD_DET_N_10.8;10.8-9;9: nets SDCARD_DET_N
net group SOC_CAN0_DIN_8.1;8.1-9;9: nets SOC_CAN0_DIN
net group SOC_CAN0_DOUT_8.1;8.1-9;9: nets SOC_CAN0_DOUT
net group SOC_PWR_REQ_12;12-10.5;10.5: nets SOC_PWR_REQ
net group SP339_UART1_CTS_10.8;10.8-9;9: nets SP339_UART1_CTS
net group SP339_UART1_RTS_10.8;10.8-9;9: nets SP339_UART1_RTS
net group SP339_UART1_RX_10.8;10.8-9;9: nets SP339_UART1_RX
net group SP339_UART1_TX_10.8;10.8-9;9: nets SP339_UART1_TX
net group SP339_UART2_CTS_10.8;10.8-9;9: nets SP339_UART2_CTS
net group SP339_UART2_RTS_10.8;10.8-9;9: nets SP339_UART2_RTS
net group SP339_UART2_RX_10.8;10.8-9;9: nets SP339_UART2_RX
net group SP339_UART2_TX_10.8;10.8-9;9: nets SP339_UART2_TX
net group SP3391_UART1_CTS_10.8;10.8-9;9: nets SP3391_UART1_CTS
net group SP3391_UART1_RTS_10.8;10.8-9;9: nets SP3391_UART1_RTS
net group SP3391_UART1_RX_10.8;10.8-9;9: nets SP3391_UART1_RX
net group SP3391_UART1_TX_10.8;10.8-9;9: nets SP3391_UART1_TX
net group SP3392_UART2_CTS_10.8;10.8-9;9: nets SP3392_UART2_CTS
net group SP3392_UART2_RTS_10.8;10.8-9;9: nets SP3392_UART2_RTS
net group SP3392_UART2_RX_10.8;10.8-9;9: nets SP3392_UART2_RX
net group SP3392_UART2_TX_10.8;10.8-9;9: nets SP3392_UART2_TX
net group SPI1_CS0_8.1;8.1-6;6: nets SPI1_CS0
net group SPI1_CS1_40PIN_12;12-10.5;10.5: nets SPI1_CS1_40PIN
net group SPI1_MISO_8.1;8.1-6;6: nets SPI1_MISO
net group SPI1_MOSI_8.1;8.1-6;6: nets SPI1_MOSI
net group SPI1_SCK_8.1;8.1-6;6: nets SPI1_SCK
net group SPI_A_CE*_8.1;8.1-6;6: nets SPI_A_CE*
net group SPI_A_SCLK_8.1;8.1-6;6: nets SPI_A_SCLK
net group SPI_A_SIN_8.1;8.1-6;6: nets SPI_A_SIN
net group SPI_A_SOUT_8.1;8.1-6;6: nets SPI_A_SOUT
net group SPI_HUB_CS_12;12-7;7: nets SPI_HUB_CS
net group SPI_HUB_MISO_12;12-7;7: nets SPI_HUB_MISO
net group SPI_HUB_MOSI_12;12-7;7: nets SPI_HUB_MOSI
net group SPI_HUB_SCK_12;12-7;7: nets SPI_HUB_SCK
net group STANDBY_REQ_N_GP109_12;12-10.A: nets STANDBY_REQ_N_GP109
net group SUSCLK_32KHZ_M2E_12;12-10.5;1A: nets SUSCLK_32KHZ_M2E
net group SUSCLK_32KHZ_M2M_12;12-10.5;1A: nets SUSCLK_32KHZ_M2M
net group SYS_RST_IN_N_12;12-10.5;10.5: nets SYS_RST_IN_N
net group SYS_RST_IN_N_CON_12;12-10.5;1A: nets SYS_RST_IN_N_CON
net group SYS_RST_IN_N_KEY_12;12-10.5;1A: nets SYS_RST_IN_N_KEY
net group SYS_RST_IN_Q_12;12-10.5;10.5: nets SYS_RST_IN_Q
net group UART1_CTS_10.8;10.8-9;9: nets UART1_CTS
net group UART1_RTS_10.8;10.8-9;9: nets UART1_RTS
net group UART1_RX_10.8;10.8-9;9: nets UART1_RX
net group UART1_TX_10.8;10.8-9;9: nets UART1_TX
net group UART2_CTS_10.8;10.8-9;9: nets UART2_CTS
net group UART2_RTS_10.8;10.8-9;9: nets UART2_RTS
net group UART2_RX_10.8;10.8-9;9: nets UART2_RX
net group UART2_TX_10.8;10.8-9;9: nets UART2_TX
net group UART5_CTS_10.8;10.8-9;9: nets UART5_CTS
net group UART5_RTS_10.8;10.8-9;9: nets UART5_RTS
net group UART5_RXD_10.8;10.8-9;9: nets UART5_RXD
net group UART5_TXD_10.8;10.8-9;9: nets UART5_TXD
net group UFS0_REF_CLK_12;12-10.5;10.5: nets UFS0_REF_CLK
net group UFS0_RST_N_12;12-10.5;10.5: nets UFS0_RST_N
net group USB_VBUS1_20;20-20;20: nets USB_VBUS1
net group USB_VBUS2_20;20-20;20: nets USB_VBUS2
net group USB_VBUS3_20;20-20;20: nets USB_VBUS3
net group USB_VBUS4_20;20-20;20: nets USB_VBUS4
net group USIM_CLK_12;12-10.5;10.5: nets USIM_CLK
net group VBUS_MON_P1_12;12-10.5;10.5: nets VBUS_MON_P1
net group VCONN_MON_P1_12;12-10.5;10.5: nets VCONN_MON_P1
net group VDD_3V3_PD_PGADJ_12;12-10.5;1A: nets VDD_3V3_PD_PGADJ
net group VDD_FAN_20;20-20;20: nets VDD_FAN
net group VIN_PWR_BAD_N_12;12-10.5;10.5: nets VIN_PWR_BAD_N
net group VIN_SHUTDOWN_N_12;12-10.5;10.5: nets VIN_SHUTDOWN_N
net group XFI0_RST_N_12;12-10.5;10.5: nets XFI0_RST_N
net group XFI1_MDC_CON_12;12-10.5;10.5: nets XFI1_MDC_CON
net group XFI1_MDIO_CON_12;12-10.5;10.5: nets XFI1_MDIO_CON
net group XFI2_MDC_CON_12;12-10.5;10.5: nets XFI2_MDC_CON
net group XFI2_MDIO_CON_12;12-10.5;10.5: nets XFI2_MDIO_CON
net group XFI3_MDC_CON_12;12-10.5;10.5: nets XFI3_MDC_CON
net group XFI3_MDIO_CON_12;12-10.5;10.5: nets XFI3_MDIO_CON

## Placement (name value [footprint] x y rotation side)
C40  4.7uF  [C0805]  70.61 93.22 270 bottom
C41  4.7uF  [C0805]  70.61 93.22 270 top
C42  4.7uF  [C0805]  68.33 93.22 270 top
C43  4.7uF  [C0805]  68.33 93.22 270 bottom
C44  120uF  [CD8P35-1]  77.09 93.22 0 top
C45  120uF  [CD8P35-1]  77.09 101.73 0 top
C46  0.1uF(100N)  [C0805]  72.64 88.52 90 top
C47  100nF  [C0603]  67.56 89.79 0 bottom
C48  4.7uF  [C0603]  64.07 84.71 180 top
C49  4.7uF  [C0603]  71.88 85.47 270 top
C50  10uF,  [C0402_PLUS]  41.4 95.12 180 bottom
C51  10uF,  [C0402_PLUS]  41.4 97.16 180 bottom
C52  1uF  [C0402]  41.4 99.19 180 bottom
C53  330uF  [TC-D]  39.75 96.77 180 top
C54  330uF  [TC-D]  39.75 91.69 180 top
C55  X/1000pF  [C0402]  69.98 89.66 90 top
C56  100nF  [C0603]  73.03 78.74 0 top
C57  1000pF  [C0603]  62.36 91 90 top
C58  4700pF  [C0402]  73.53 76.83 90 top
C59  10nF  [C0402]  71.25 82.3 0 top
C60  1uF  [C0603]  66.17 81.41 270 top
C61  2200pF  [C0402]  63.3 92.96 180 top
C62  X/0.1uF 50V  [C0603]  73.53 81.41 270 top
C63  22uF  [C1206]  76.33 82.3 270 bottom
C64  0.1uF,  [C0402]  78.04 82.3 270 top
C65  22uF  [C1206]  76.33 82.3 270 top
C66  1uF  [C0402]  81.41 85.72 270 top
C67  0.22 uF  [C0402]  82.93 84.71 270 top
C68  X/1000pF  [C0402]  80.9 80.01 180 top
C69  33pF  [C0402]  79.25 87.25 180 top
C70  22uF,  [C0402_PLUS]  82.42 78.74 180 top
C71  22uF,  [C0402_PLUS]  82.42 77.34 180 bottom
C72  10uF,  [C0402_PLUS]  82.42 78.74 180 bottom
C73  10uF,  [C0402_PLUS]  82.42 77.34 180 top
C76  0.1uF,  [C0402]  65.28 64.77 270 top
C77  0.22 uF  [C0402]  70.36 66.17 270 top
C82  1uF  [C0402]  69.6 68.58 270 top
C84  33pF  [C0402]  67.31 70.87 270 top
C103  220 uF  [TC-8P3X8P3X10P5M]  78.49 133.22 90 bottom
C104  0.039uF  [C0402]  74.17 106.93 90 top
C105  120pF  [C0402]  76.45 106.93 90 top
C106  0.012uF  [C0805]  74.93 109.09 0 bottom
C107  0.033uF  [C0402]  79.88 106.93 90 top
C108  1000pF  [C0402]  77.6 106.93 270 top
C109  100pF  [C0402]  78.74 112.27 180 bottom
C110  100nF  [C0603]  71.37 107.19 270 top
C111  100nF  [C0603]  71.25 115.44 0 top
C112  1uF  [C0402]  75.25 115.44 0 top
C113  100nF  [C0603]  78.11 116.08 180 top
C114  100nF  [C0603]  73.53 116.14 90 top
C115  22uF  [C0805]  82.04 126.75 0 top
C116  22uF  [C0805]  82.04 126.62 0 bottom
C117  22uF  [C0805]  82.04 124.84 0 top
C118  220 uF  [TC-8P3X8P3X10P5M]  65.66 115.25 270 top
C119  10uF  [C1206]  63.12 114.68 270 bottom
C120  10uF  [C1206]  67.69 114.68 270 bottom
C121  10uF  [C1206]  65.41 114.68 270 bottom
C122  4.7uF  [C0805]  17.02 107.7 270 bottom
C123  1000PF  [C1808]  17.4 119.76 90 bottom
C124  1000PF  [C1808]  10.79 129.41 180 bottom
C125  1uF  [C0603]  23.37 106.81 0 bottom
C126  4.7uF  [C0805]  59.44 103.63 0 bottom
C244  0.22 uF  [C0402]  92.1 136.91 270 top
C380  X/10nF  [C0402]  91.57 86.61 0 top
C382  0.1uF  [C0402]  90.3 75.06 270 bottom
C396  0.1uF  [C0402]  52.32 83.19 270 bottom
C397  0.1uF  [C0402]  52.07 88.77 0 top
C398  0.1uF  [C0402]  48.77 86.23 90 bottom
C399  0.1uF  [C0402]  55.37 88.77 0 top
C400  0.1uF  [C0402]  58.29 88.77 0 top
C401  0.1uF  [C0402]  49.15 88.77 180 top
C402  0.1uF  [C0402]  55.37 80.77 180 top
C403  0.1uF  [C0402]  58.42 80.01 180 top
C408  10uF  [C1206]  41.4 104.14 180 top
C412  10uF  [C1206]  41.4 106.43 180 top
C413  0.1uF,  [C0402]  45.34 106.43 0 top
C414  10uF,  [C0402_PLUS]  56.77 69.47 270 top
C415  10uF,  [C0402_PLUS]  47.62 104.65 180 top
C416  0.1uF  [C0402]  56.77 71.5 270 top
C417  0.1uF  [C0402]  47.62 106.43 180 top
C418  0.1uF  [C0402]  56.77 73.53 270 top
C419  4.7uF  [C0603]  49.66 80.39 90 top
C420  0.1uF  [C0402]  50.93 80.26 90 top
C421  1uF  [C0402]  45.72 76.33 180 top
C422  390pF  [C0402]  45.72 78.61 180 top
C423  390pF  [C0402]  52.2 80.26 90 top
C424  0.1uF  [C0402]  45.72 72.39 180 top
C425  0.1uF  [C0402]  45.72 75.18 180 top
C426  4.7uF  [C0603]  43.69 80.14 270 top
C454  1uF  [C0402]  28.7 98.68 270 bottom
C456  0.1uF  [C0402]  26.77 98.17 180 bottom
C457  0.1uF  [C0402]  29.87 98.68 90 bottom
C459  0.1uF  [C0402]  26.77 99.31 180 bottom
C461  0.1uF  [C0402]  25.27 98.55 90 bottom
C466  0.47uF  [C0402]  92.46 114.43 90 bottom
C467  0.47uF  [C0402]  91.31 114.43 90 bottom
C468  22uF  [C1206]  87.25 103.5 0 top
C471  220pF  [C0402]  85.09 109.98 0 top
C472  22uF,  [C0402_PLUS]  89.28 110.62 270 top
C473  1uF  [C0402]  24.89 83.06 270 bottom
C475  0.1uF  [C0402]  26.04 83.06 90 bottom
C476  1uF  [C0402]  84.2 108.46 0 top
C477  X/1000pF  [C0402]  85.09 112.52 0 top
C478  33pF  [C0402]  82.68 105.03 0 top
C489  10uF  [C1206]  88.52 101.73 270 bottom
C495  220uF  [TC-11X10P3X16P5M]  16.64 122.17 0 top
C496  X/220uF  [TC-11X10P3X16P5M]  16.64 111.38 0 top
C497  0.039uF  [C0402]  30.48 101.85 90 top
C498  220 uF  [TC-8P3X8P3X10P5M]  48.39 120.4 270 top
C499  220 uF  [TC-8P3X8P3X10P5M]  57.02 120.4 270 top
C500  10uF  [C1206]  57.91 120.9 0 bottom
C501  10uF  [C1206]  57.91 123.19 0 bottom
C502  4.7uF  [C0805]  47.88 113.16 90 bottom
C503  22uF  [C0805]  52.83 108.97 90 top
C504  1uF  [C0402]  45.59 120.65 0 bottom
C505  100nF  [C0603]  35.88 107.44 0 bottom
C506  100nF  [C0603]  26.92 110.24 0 top
C507  100nF  [C0603]  37.85 110.49 180 top
C508  1000PF  [C1808]  15.75 67.82 180 top
C509  0.012uF  [C0805]  34.29 101.22 90 top
C510  0.1uF,  [C0402]  29.72 110.43 180 top
C511  100pF  [C0402]  32.77 101.85 270 top
C512  680pF  [C0402]  35.81 101.85 270 top
C513  0.01uF  [C0402]  37.34 101.09 180 top
C514  1uF  [C0402]  31.88 110.43 0 top
C515  X/0.1uF  [C0402]  49.28 110.24 90 top
C516  100nF  [C0603]  27.56 104.65 270 top
C568  4.7uF  [C1210]  18.67 114.3 0 bottom
C569  4.7uF  [C1210]  18.67 111.12 0 bottom
C604  22uF,  [C0402_PLUS]  90.68 110.62 270 top
C605  X/1000pF  [C0603]  70.87 124.08 90 top
C618  X/1000pF  [C0603]  74.3 121.79 180 top
C619  X/1000pF  [C0603]  30.05 114.71 0 top
C620  X/1000pF  [C0603]  39.6 114.94 180 top
C621  10uF  [C1206]  58.67 103.76 0 top
C622  2.2uF  [C0805]  47.89 113.04 90 top
C635  22uF  [C1206]  87.25 101.22 0 top
C636  0.1uF  [C0402]  87.63 105.16 0 top
CN1  3,90D,MALE,ECH381RM-03P-BK,  [TBLOCK-3P-RDM-3P81M-T7P2M]  5.54 114.17 270 top
CN19  4*1P 210-91-04GB01  [JH4-HD]  62.99 73.79 180 top
CN35  HL-VGA-9MX2  [DB_HL-VGA9MX2-H28_43MM]  6.8 85.47 270 top
D1  SS1060HEWS  [TS-SOD323-1P8X0P6X0P75M]  70.74 104.52 0 top
D2  PMEG2010AEB  [TS-SOD523-5]  75.44 116.71 180 top
D3  SBM56LAFC,  [TS-SMAF-4P7X2P5X1P1M]  73.28 118.94 0 top
D4  BAT54CW  [TS-SOT323]  66.55 105.28 90 bottom
D6  TV50C360JB-CRHF,  [TS-DO214AB]  12.95 117.6 270 bottom
D7  TV50C360JB-CRHF,  [TS-DO214AB]  10.29 125.09 180 bottom
D9  1N4148WS  [TS-MSOD80]  41.4 108.46 0 top
D13  1N4148WS  [TS-MSOD80]  41.53 101.85 0 top
D28  SBM56LAFC,  [TS-SMAF-4P7X2P5X1P1M]  29.59 112.39 0 top
D29  SBM56LAFC,  [TS-SMAF-4P7X2P5X1P1M]  36.32 112.65 180 top
D31  SS1060HEWS  [TS-SOD323-1P8X0P6X0P75M]  25.91 101.73 0 top
D49  TV50C360JB-CRHF,  [TS-DO214AB]  12.83 107.31 90 bottom
D50  SMBJ18CA  [ESD-2P-SMA]  22.23 86.61 180 top
D51  SMBJ18CA  [ESD-2P-SMA]  22.23 92.96 180 top
D52  SMBJ18CA  [ESD-2P-SMA]  22.23 89.79 180 top
D53  SMBJ18CA  [ESD-2P-SMA]  22.23 96.14 180 top
D54  SMBJ18CA  [ESD-2P-SMA]  22.23 99.31 180 top
D55  SMBJ18CA  [ESD-2P-SMA]  22.23 70.74 180 top
D56  SMBJ18CA  [ESD-2P-SMA]  22.23 77.09 180 top
D57  SMBJ18CA  [ESD-2P-SMA]  22.23 73.91 180 top
D58  SMBJ18CA  [ESD-2P-SMA]  22.23 80.26 180 top
D59  SMBJ18CA  [ESD-2P-SMA]  22.23 83.44 180 top
FB1  50 Ohm@(100Mhz)  [L1206]  83.82 132.08 90 bottom
H2  X/MH  [MH217D138]  5 135 0 top
HM3  F55M30-400736P1D4BM  [MH276D150-T4P05M]  83.26 119.18 180 bottom
L1  10.8mohm_3.3uH_10A  [SCOILA-115X103]  51.94 95.89 0 top
L3  2.2uH.Idc=5.5A.DCR=29mohm  [SCOILA-48P5X47]  86.11 81.41 90 top
L4  DCR=28m ohm,ZPWM-6030M-3R3M,  [SCOILA-73X68]  76.07 66.67 180 top
L6  121-L_COIL-2P  [SCOILA-115X100-1]  66.93 133.6 180 top
L40  2.2 uH  [SCOILA-2P5X2X1P2M]  87.38 111.12 270 top
L41  1.5 uH  [SCOILA-17X17P9X7M]  34.29 130.05 90 top
M2  (TF)Boss.M2.0.*6.5+1.15mm.Sn  [MH197D138-1]  84.48 96.65 0 top
NOREF  -  [unnamed]  15 145 0 top
NOREF#2  -  [unnamed#2]  5 145 0 top
NOREF#3  -  [#3]  33.02 -43.18 0 top
NOREF#4  -  [unnamed]  4.06 128.27 0 top
NOREF#5  -  [#3]  87 69.85 0 top
NOREF#6  -  [unnamed]  4.06 128.27 180 bottom
NOREF#7  -  [unnamed]  15 145 180 bottom
Q3  NTS4001N,  [TS-SOT323-2X1P25X1M]  56.52 65.66 180 top
Q4  NTS4001N,  [TS-SOT323-2X1P25X1M]  53.98 65.66 0 top
Q6  P0706BK  [TS-MOSFET5X6X1P2]  68.83 97.92 270 top
Q7  P0706BK  [TS-MOSFET5X6X1P2]  61.85 97.41 0 top
Q8  NTS4001N,  [TS-SOT323-2X1P25X1M]  44.83 88.39 270 bottom
Q9  NTS4001N,  [TS-SOT323-2X1P25X1M]  91.19 79.12 180 top
Q12  BSC0925ND  [TS-MOSFET5X6-1]  65.91 125.48 270 top
Q13  BSC0925ND  [TS-MOSFET5X6-1]  75.56 125.09 90 top
Q14  PJX138KA_R1_00001,  [TS-SOT563_6-4]  70.87 111.89 0 top
Q15  NTS4001N,  [TS-SOT323-2X1P25X1M]  66.55 105.28 90 top
Q16  NTS4001N,  [TS-SOT323-2X1P25X1M]  77.47 135.89 180 top
Q17  NTS4001N,  [TS-SOT323-2X1P25X1M]  23.37 104.01 0 bottom
Q18  NTS4001N,  [TS-SOT323-2X1P25X1M]  84.45 90.42 270 top
Q19  NTS4001N,  [TS-SOT323-2X1P25X1M]  63.75 102.74 90 top
Q20  NTS4001N,  [TS-SOT323-2X1P25X1M]  62.99 105.41 90 top
Q21  FDS6681Z  [SOP8B-150]  58.29 110.49 0 top
Q38  NTS4001N,  [TS-SOT323-2X1P25X1M]  90.55 79.76 0 bottom
Q40  NTS4001N,  [TS-SOT323-2X1P25X1M]  87 68.96 0 bottom
Q41  NTS4001N,  [TS-SOT323-2X1P25X1M]  89.79 68.96 0 bottom
Q52  NTS4001N,  [TS-SOT323-2X1P25X1M]  43.18 71.75 0 top
Q62  FDS6681Z  [SOP8B-150]  52.32 120.02 180 bottom
Q63  FDS6681Z  [SOP8B-150]  52.2 110.49 0 bottom
Q64  131-N_MOS9P-PG1H10ATL  [TS-MOSFET-11P68X9P9X2P4M-8P]  17.65 133.1 90 top
Q65  P0406AK  [TS-MOSFET5X6X1P2]  40.26 118.55 270 top
Q66  MMBT3904W,  [TS-SOT323-2X1P25X1P1M]  48.13 118.24 0 bottom
Q67  NTS4001N,  [TS-SOT323-2X1P25X1M]  45.59 116.84 180 bottom
Q68  131-N_MOS9P-PG1H10ATL  [TS-MOSFET-11P68X9P9X2P4M-8P]  51.05 132.21 270 top
Q73  DMT10H015LCG  [DFN8E-3P3X3P3X0P85M]  18.16 104.14 270 bottom
R23  0ohm,  [R0402]  58.55 66.67 270 top
R24  100K  [R0402]  58.55 64.64 270 top
R27  X/10  [R0805]  49.15 65.15 90 top
R28  X/10  [R0805]  51.18 65.15 90 top
R29  10  [R0805]  41.4 90.55 0 bottom
R30  0ohm,  [R0402]  74.17 87.88 270 top
R31  100K  [R0402]  69.72 81.92 270 top
R32  100K  [R0402]  68.58 81.92 90 top
R33  0ohm,  [R0402]  66.55 89.66 270 top
R34  10  [R0402]  64.52 83.44 180 top
R35  0ohm,  [R0402]  65.28 89.66 270 top
R36  0ohm,  [R0402]  67.69 89.66 270 top
R37  10-R  [R1206]  41.91 92.71 180 bottom
R38  10K  [R0402]  71.12 89.66 90 top
R39  2K  [R0402]  68.83 89.66 270 top
R40  0ohm,  [R0402]  63.75 89.66 270 top
R41  2.2  [R0805]  59.82 91.19 0 top
R42  49.9K  [R0402]  60.39 89.66 0 top
R43  0ohm,  [R0402]  71.25 76.83 270 top
R44  7.5K  [R0402]  72.39 76.83 90 top
R45  X/0  [R0402]  71.25 80.01 180 top
R46  0ohm,  [R0402]  64.9 81.92 90 top
R47  X/0  [R0402]  71.25 81.15 0 top
R48  0ohm,  [R0402]  72.14 83.44 0 top
R49  1.69K  [R0603]  73.91 84.33 90 top
R50  0  [R0603]  68.83 79.12 0 top
R51  10  [R0805]  41.4 88.52 0 bottom
R52  0ohm,  [R0402]  77.72 87.5 270 top
R53  X/0ohm,  [R0402]  76.58 87.5 270 top
R54  0ohm,  [R0402]  78.87 85.72 90 top
R55  100  [R0402]  81.28 87.25 180 top
R56  40.2K  [R0402]  79.25 88.39 180 top
R57  20K  [R0402]  80.01 85.72 270 top
R58  X/1  [R0603]  82.8 81.28 270 top
R59  10-R  [R1206]  86.74 76.33 0 top
R60  10  [R0805]  90.81 74.42 0 top
R61  10  [R0805]  90.81 76.45 0 top
R63  0ohm,  [R0402]  66.17 68.58 270 top
R64  10-R  [R1206]  82.17 65.79 90 top
R66  100  [R0402]  69.6 70.87 90 top
R67  40.2K  [R0402]  68.45 70.87 270 top
R68  8.87K  [R0402]  68.45 68.58 270 top
R69  X/2.2  [R0805]  68.83 121.67 0 top
R70  0ohm,  [R0402]  67.31 68.58 90 top
R72  0ohm,  [R0402]  80.9 81.53 0 bottom
R73  10K  [R0402]  78.99 81.53 0 bottom
R91  27.4K  [R0402]  75.31 106.93 90 top
R92  4.87K  [R0402]  78.74 106.93 270 top
R93  2  [R0805]  69.6 107.06 90 top
R94  15 m ohm  [R1206]  71.12 123.95 270 bottom
R95  100K  [R0402]  67.69 107.57 270 top
R96  10K  [R0402]  66.42 107.57 270 top
R97  0ohm,  [R0402]  60.96 127.13 90 top
R98  0ohm,  [R0402]  70.61 127.13 90 top
R99  0ohm,  [R0402]  79.88 123.57 270 top
R100  0ohm,  [R0402]  72.2 121.54 270 top
R101  0ohm,  [R0402]  81.03 111 270 top
R102  93.1 k ohm  [R0402]  73.03 106.93 270 top
R103  280 k ohm  [R0402]  81.03 108.97 90 top
R104  20K  [R0402]  81.03 106.93 270 top
R105  5.1k  [R0402]  70.23 109.22 180 top
R106  0ohm,  [R0402]  67.44 81.92 270 top
R107  100K  [R0402]  68.2 109.22 0 top
R108  0ohm,  [R0402]  71.75 109.73 90 top
R109  100K  [R0402]  67.69 107.57 270 bottom
R110  X/470  [R0603]  80.14 133.48 180 top
R111  X/470  [R0603]  80.14 135 180 top
R112  68K  [R0402]  21.34 108.2 0 bottom
R113  47K  [R0402]  23.37 108.2 0 bottom
R114  X/100K  [R0402]  87.25 91.44 0 top
R115  47K  [R0402]  84.96 92.33 0 top
R116  0ohm,  [R0402]  87.25 90.3 180 top
R117  0ohm,  [R0402]  67.44 102.23 90 top
R118  100K  [R0402]  66.29 102.23 90 top
R119  100K  [R0402]  59.56 106.05 0 top
R120  10K  [R0402]  61.53 103.19 270 top
R121  X/470  [R0603]  63.63 108.2 270 top
R122  X/470  [R0603]  62.1 108.2 270 top
R304  0ohm,  [R0402]  90.42 98.4 180 top
R339  10K  [R0402]  52.32 83.19 90 top
R425  2K  [R0402]  28.19 101.85 270 top
R455  10K  [R0402]  90.81 81.92 180 bottom
R457  X/1M  [R1206]  21.84 100.08 180 bottom
R459  10K  [R0402]  43.94 109.22 90 top
R462  10K  [R0402]  90.3 77.09 270 bottom
R463  10K  [R0402]  93.73 72.64 90 bottom
R469  10K  [R0402]  86.74 66.67 0 bottom
R470  10K  [R0402]  91.69 68.45 270 bottom
R477  2K  [R0402]  73.03 104.9 90 top
R479  100  [R0603]  36.58 109.6 270 bottom
R480  X/10K  [R0402]  92.58 99.85 180 top
R481  X/10K  [R0402]  92.58 100.97 0 top
R497  0ohm,  [R0402]  93.6 68.45 90 bottom
R501  10K  [R0402]  86.74 65.53 0 bottom
R502  10K  [R0402]  86.74 64.39 0 bottom
R503  100K  [R0402]  84.58 64.9 90 bottom
R513  100  [R0603]  35.12 109.6 270 bottom
R515  100  [R0603]  79.44 114.34 90 bottom
R521  10K  [R0402]  54.1 83.57 0 bottom
R522  100K  [R0402]  53.47 83.19 90 top
R523  10K  [R0402]  50.42 83.19 90 bottom
R524  100K  [R0402]  50.42 83.19 270 top
R525  10K  [R0402]  47.5 86.23 90 top
R526  10K  [R0402]  60.07 81.15 90 top
R527  100K  [R0402]  55.37 79.63 180 top
R529  10K  [R0402]  25.27 68.45 0 bottom
R546  X/10K  [R0402]  49.28 83.19 90 top
R547  10K  [R0402]  59.94 86.23 90 top
R548  10K  [R0402]  47.75 83.06 180 top
R549  10K  [R0402]  44.83 83.06 0 top
R550  47K  [R0402]  45.72 73.91 0 top
R551  10K  [R0402]  43.69 69.47 0 top
R552  100K  [R0402]  45.72 77.47 0 top
R553  100K  [R0402]  45.72 70.1 0 top
R554  10K  [R0402]  45.72 71.25 180 top
R555  100K  [R0402]  42.8 75.18 0 top
R556  10K  [R0402]  42.8 74.04 180 top
R557  10K  [R0402]  53.34 80.26 270 top
R558  10K  [R0402]  54.74 68.96 0 top
R559  10K  [R0402]  52.7 68.96 180 top
R560  10K  [R0402]  54.48 72.9 90 bottom
R561  100K  [R0402]  56.77 75.56 270 top
R608  0ohm,  [R0402]  21.08 98.3 180 bottom
R610  0ohm,  [R0402]  21.08 97.16 180 bottom
R612  0ohm,  [R0402]  21.46 93.85 270 bottom
R617  0ohm,  [R0402]  24.89 87.25 270 bottom
R620  0ohm,  [R0402]  26.04 87.25 270 bottom
R624  0ohm,  [R0402]  92.58 93.47 180 top
R625  0ohm,  [R0402]  92.58 94.61 180 top
R649  10K  [R0402]  87.88 106.43 90 bottom
R651  0ohm,  [R0402]  84.45 104.52 90 top
R652  10-R  [R1206]  92.46 110.24 270 top
R653  0ohm,  [R0402]  87.88 108.46 90 bottom
R654  X/1  [R0603]  84.58 111.25 180 top
R655  100  [R0402]  82.3 106.55 270 top
R656  40.2K  [R0402]  82.68 103.89 0 top
R657  0ohm,  [R0402]  84.45 106.55 270 top
R658  11K  [R0402]  83.38 106.55 90 top
R663  0ohm,  [R0402]  21.08 82.42 180 bottom
R665  0ohm,  [R0402]  21.08 81.28 180 bottom
R667  0ohm,  [R0402]  21.46 78.11 270 bottom
R671  0ohm,  [R0402]  25.02 71.88 270 bottom
R674  0ohm,  [R0402]  26.16 71.88 270 bottom
R682  0ohm,  [R0402]  92.58 103.25 0 top
R687  27.4K  [R0402]  31.62 101.85 90 top
R688  8.06K  [R0402]  37.34 102.23 0 top
R689  0ohm,  [R0402]  23.88 126.36 90 top
R690  0ohm,  [R0402]  32.77 120.4 180 top
R691  0ohm,  [R0402]  35.81 115.7 90 top
R692  0ohm,  [R0402]  46.74 138.18 180 top
R693  93.1 k ohm  [R0402]  29.34 101.85 270 top
R694  280 k ohm  [R0402]  37.34 104.65 180 top
R695  100K  [R0402]  46.35 113.54 90 bottom
R696  0ohm,  [R0402]  37.34 105.79 0 top
R697  11.8K  [R0402]  37.34 103.38 0 top
R698  2.5 m ohm  [R2512-7]  34.23 116.33 270 bottom
R699  20K  [R0402]  48.01 115.95 180 bottom
R700  100K  [R0402]  27.3 106.93 0 top
R701  2  [R0805]  25.78 104.52 270 top
R702  47K  [R0402]  48.26 120.65 0 bottom
R703  10K  [R0402]  45.59 119.51 180 bottom
R704  100K  [R0402]  45.21 113.92 90 bottom
R705  240K  [R0402]  91.57 87.76 0 top
R706  21.5K  [R0402]  49.28 108.2 90 top
R707  10K  [R0402]  48.2 109.79 0 bottom
R708  10K  [R0402]  44.83 112.01 0 top
R738  0ohm,  [R0402]  90.42 94.61 180 top
R739  0ohm,  [R0402]  90.42 97.16 180 top
R758  0ohm,  [R0402]  92.58 96.01 180 top
R759  0ohm,  [R0402]  92.58 97.16 180 top
R760  0ohm,  [R0402]  92.58 102.11 180 top
R782  10K  [R0402]  50.67 68.96 0 top
R801  100K  [R0402]  21.46 102.49 90 bottom
R803  100K  [R0402]  37.34 106.93 180 top
R815  100  [R0603]  77.98 114.34 90 bottom
R841  0ohm,  [R0402]  42.8 113.16 180 top
R842  0ohm,  [R0402]  78.17 119.57 270 top
R843  X/2.2  [R0805]  77.34 121.54 180 top
R844  X/2.2  [R0805]  26.92 114.78 0 top
R845  X/2.2  [R0805]  42.65 114.68 180 top
R848  10K  [R0402]  56.77 77.42 90 top
R849  10K  [R0402]  48.64 68.96 180 top
R850  0ohm,  [R0402]  61.98 71.25 180 top
R851  X/0ohm,  [R0402]  64.01 71.25 0 top
TP32  X/TP1  [TP20]  92.33 73.03 90 bottom
TP33  X/TP1  [TP20]  93.73 74.04 180 bottom
TP34  X/TP1  [TP20]  95.12 78.99 180 bottom
TP36  X/TP1  [TP20]  92.58 67.82 180 bottom
TP48  X/TP1  [TP20]  94.36 64.52 180 bottom
TP49  X/TP1  [TP20]  95.12 64.52 180 bottom
TP54  X/TP1  [TP20]  47.37 88.77 90 top
TP55  X/TP1  [TP20]  55.5 81.92 0 bottom
TP56  X/TP1  [TP20]  59.94 87.63 180 top
TP57  X/TP1  [TP20]  57.66 76 180 top
TP58  X/TP1  [TP20]  60.2 82.93 180 top
TP59  X/TP1  [TP20]  56.77 79.63 180 top
TP62  X/TP1  [TP20]  23.88 68.2 180 bottom
TP66  X/TP1  [TP20]  49.15 106.55 0 top
TP67  X/TP1  [TP20]  46.35 83.06 180 top
TP91  X/TP1  [TP20]  54.48 107.7 0 top
TP92  X/TP1  [TP20]  43.94 110.49 270 top
TP98  X/TP1  [TP20]  92.58 122.81 180 top
TP101  X/TP1  [TP20]  36.7 107.82 0 top
U2  MIC2128YML-TR  [QFN16F-3X3-8]  68.33 85.72 270 top
U3  14-P_R-MP2384GG-0  [QFN11F-2X2X1M]  80.39 82.55 0 top
U8  28 PINP LM5176RHFR  [VQFN28F-5X4X1M]  76.45 111.38 0 top
U77  6 SN74LVC1G11DCKR  [TS-SC70_6-1]  92.71 75.82 270 bottom
U97  SN74AUP1G04DRLR  [TS-SOT553_5-1P7X1P3X0P6M]  52.7 86.11 0 bottom
U98  SN74LVC1G126DCKR  [TS-SC70_5-4]  52.58 86.36 0 top
U99  SN74AUP1G04DRLR  [TS-SOT553_5-1P7X1P3X0P6M]  50.29 86.23 0 bottom
U100  SN74LVC1G126DCKR  [TS-SC70_5-4]  55.37 86.36 0 top
U101  SN74LVC1G126DCKR  [TS-SC70_5-4]  58.17 86.36 0 top
U102  6 SN74LVC1G11DCKR  [TS-SC70_6-1]  49.78 86.36 0 top
U103  14-T_C_L-74LVC1G86SE-7  [TS-SOT353_5-T1P1M]  55.37 82.8 180 top
U104  6 SN74LVC1G11DCKR  [TS-SC70_6-1]  58.29 82.42 180 top
U107  CYPD4226-40LQXIT  [QFN40F-6X6X0P6M]  51.44 74.3 180 top
U108  5,TPS2065DBVR,  [TS-SOT23_5]  46.61 80.77 90 top
U117  14-P_R-MP2384GG-0  [QFN11F-2X2X1M]  87 107.57 90 top
